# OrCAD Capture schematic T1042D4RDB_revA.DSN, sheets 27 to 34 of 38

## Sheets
27 27 PCIe: size B
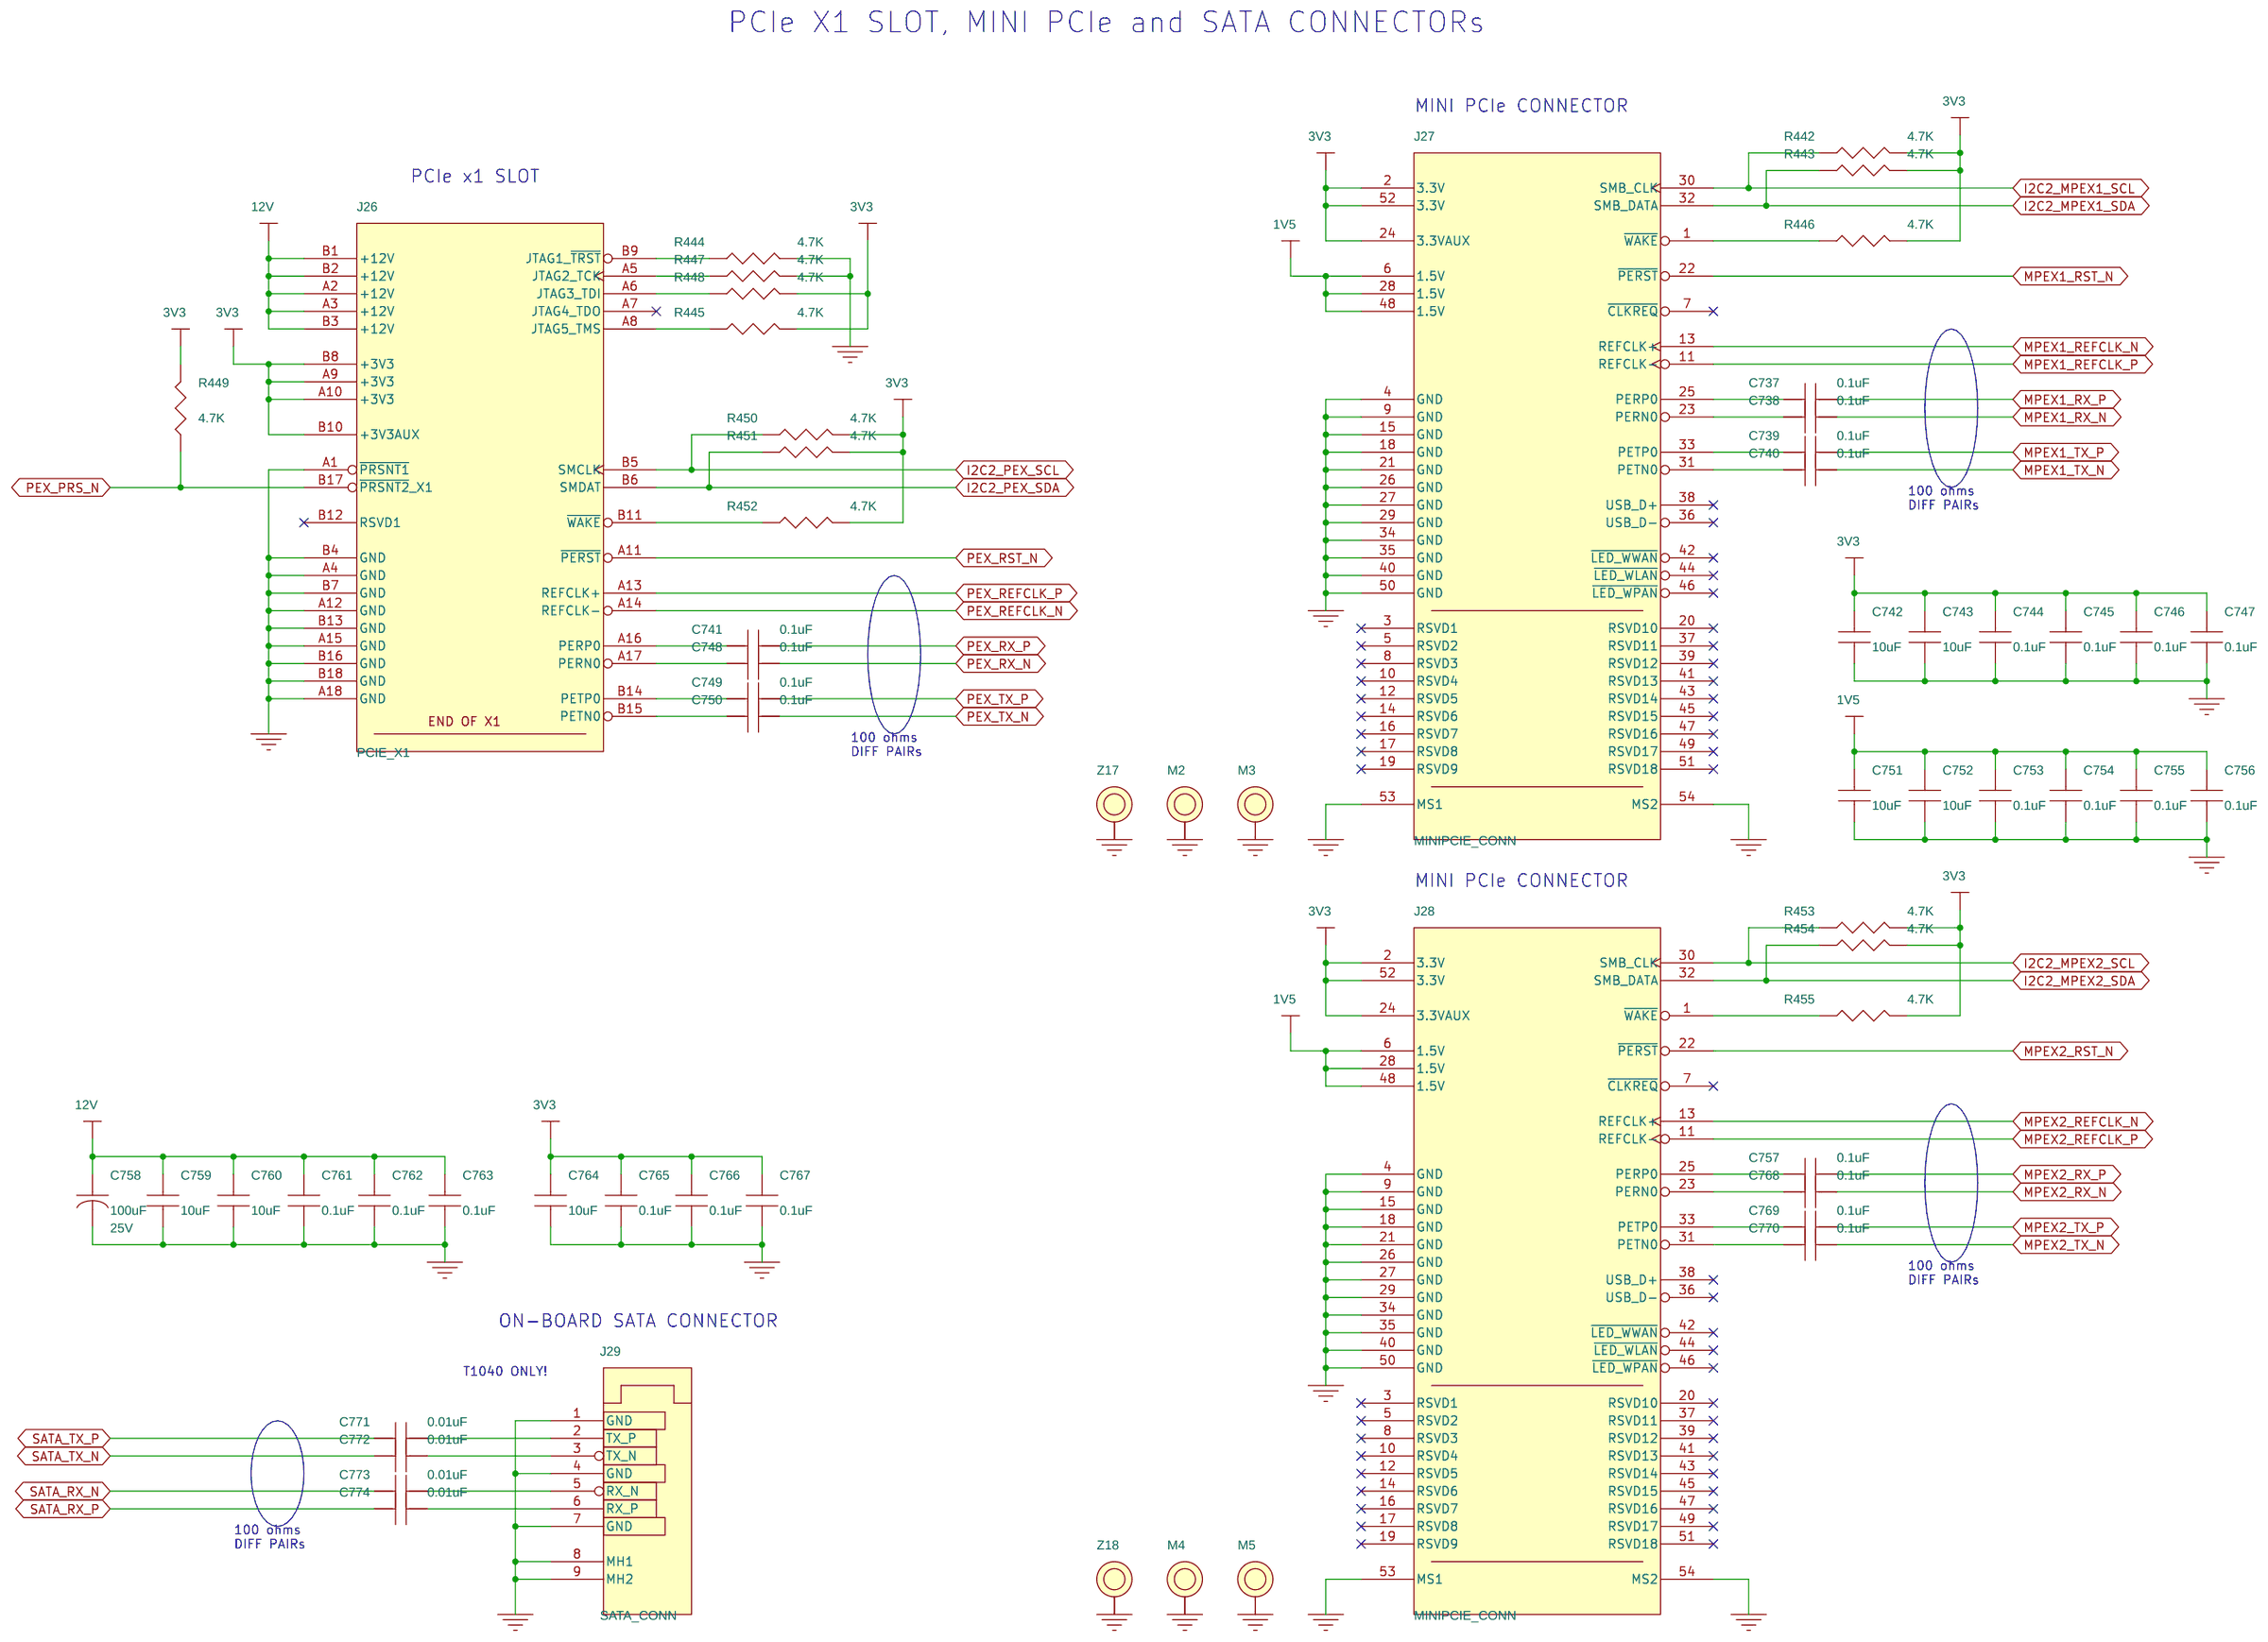
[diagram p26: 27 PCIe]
28 28 Aurora: size B
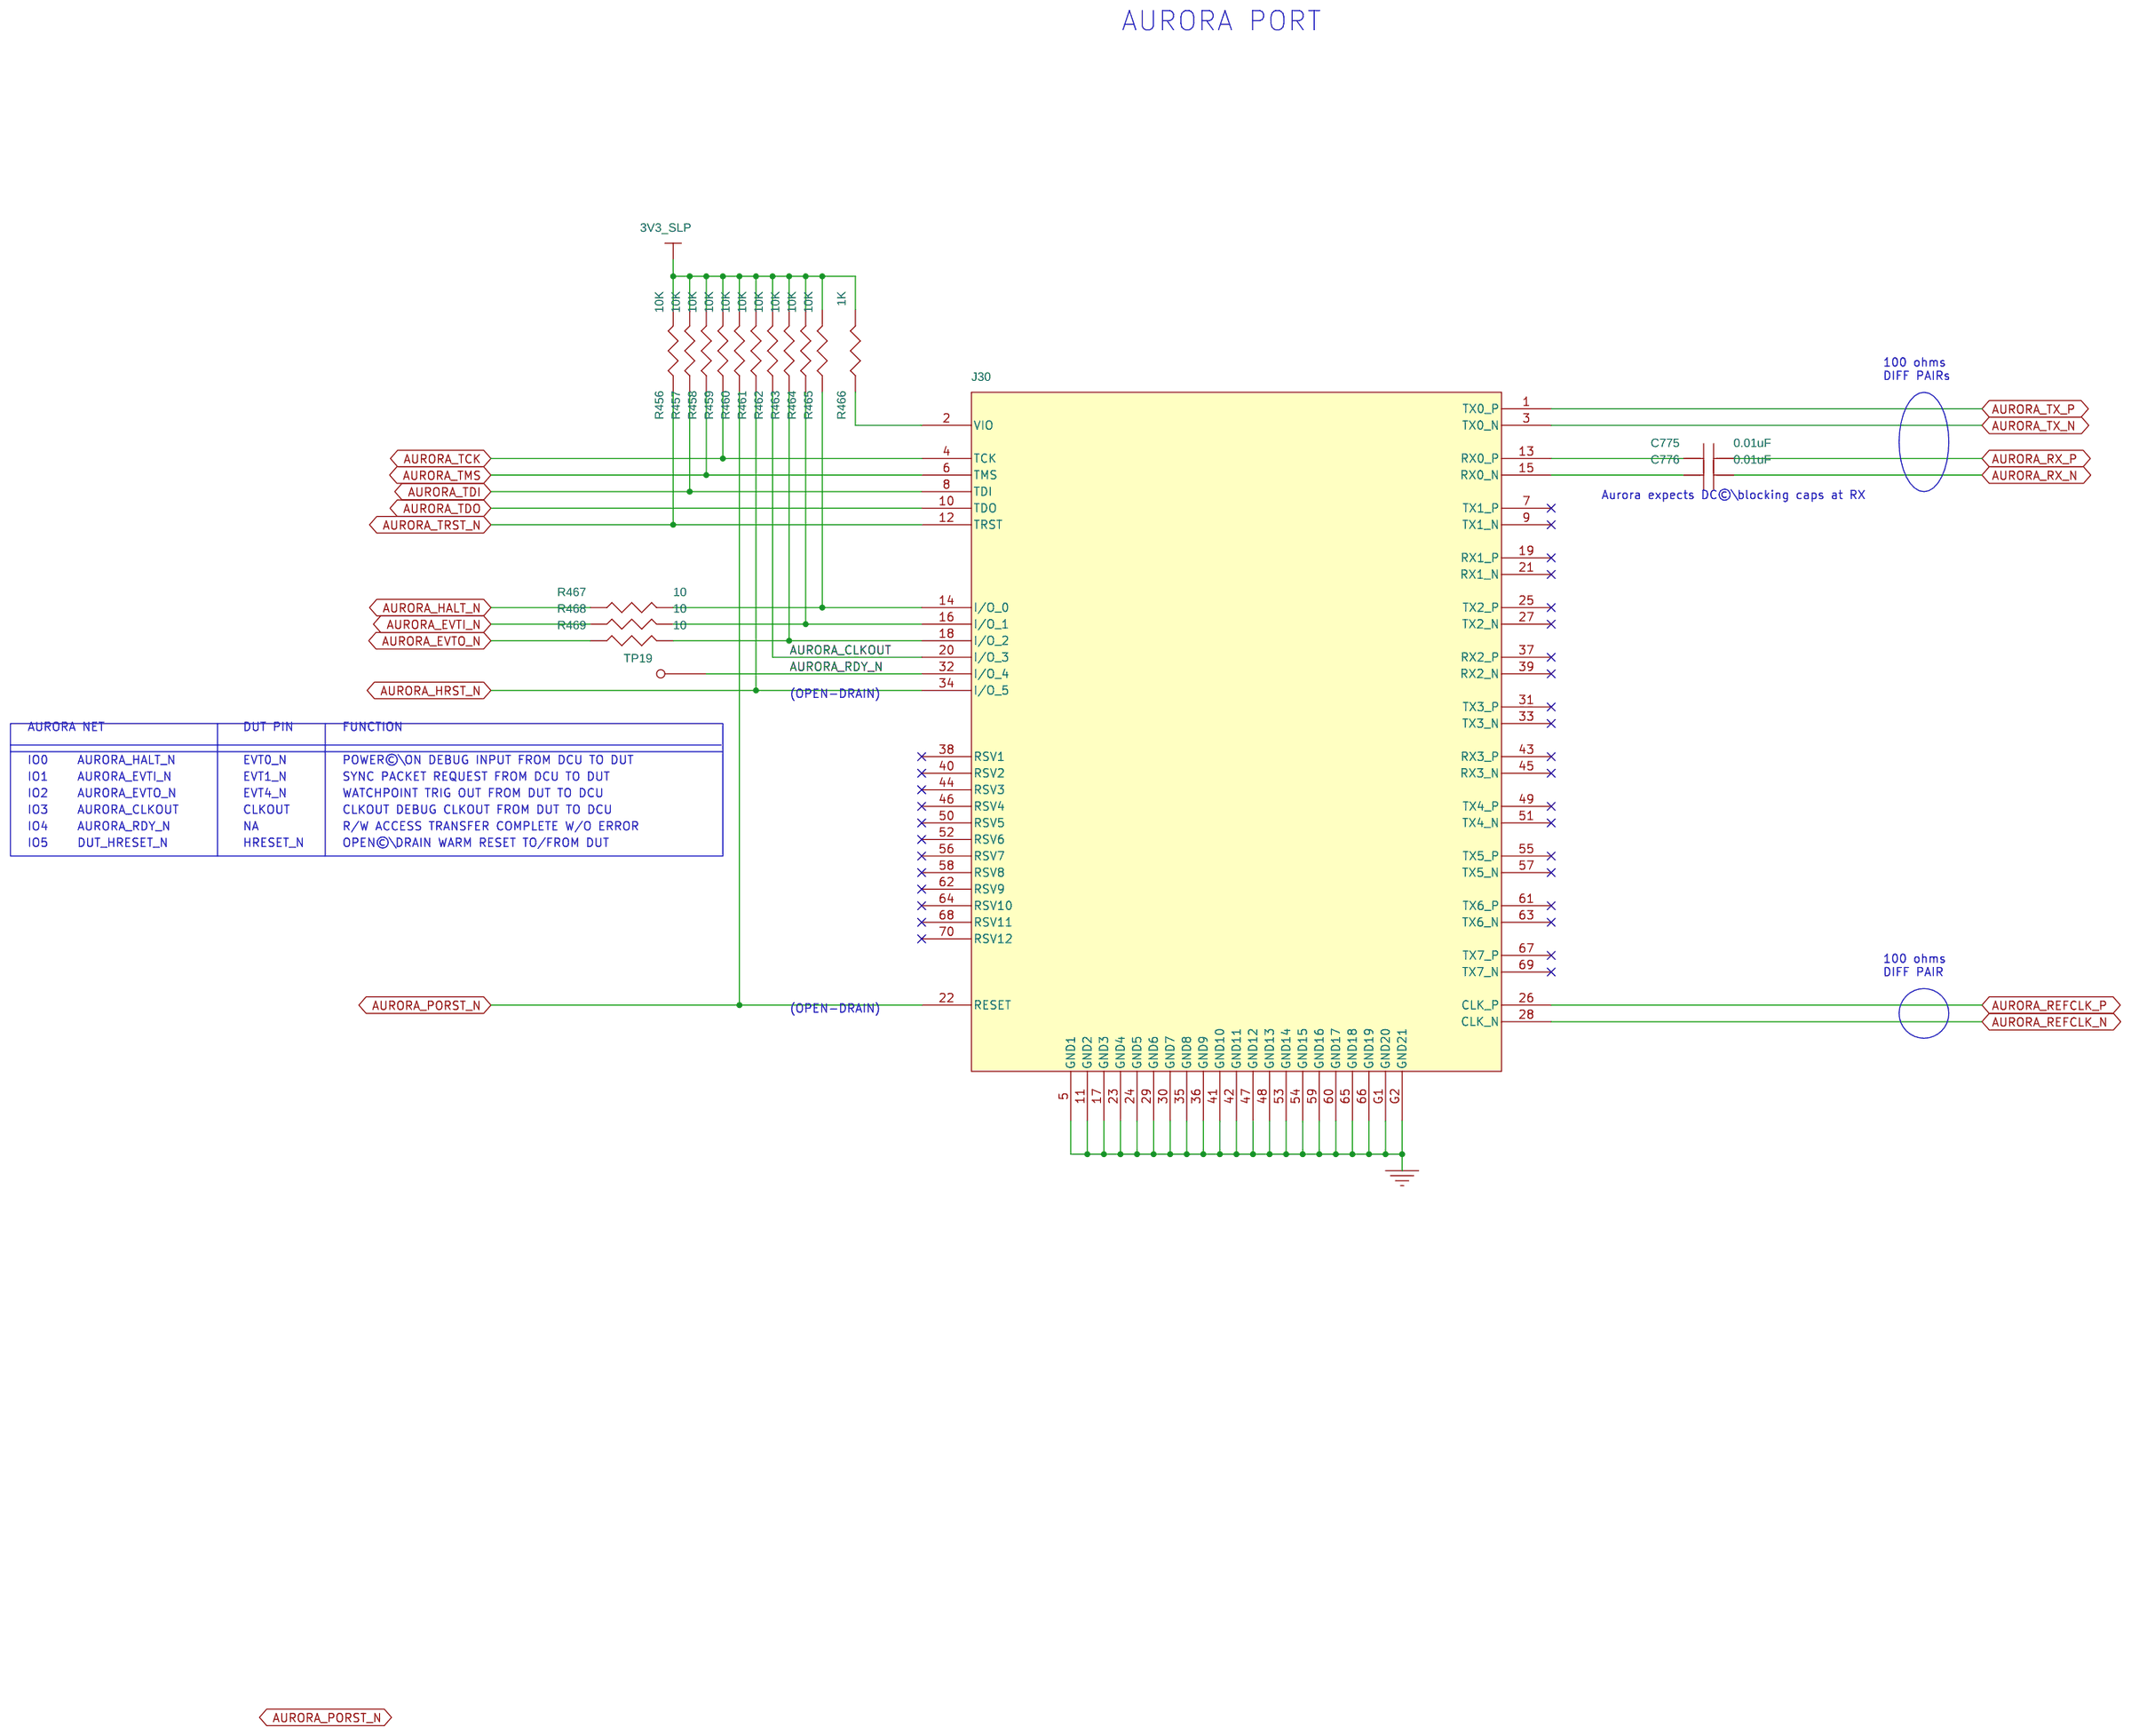
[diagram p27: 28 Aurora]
29 29 CPLD: size B
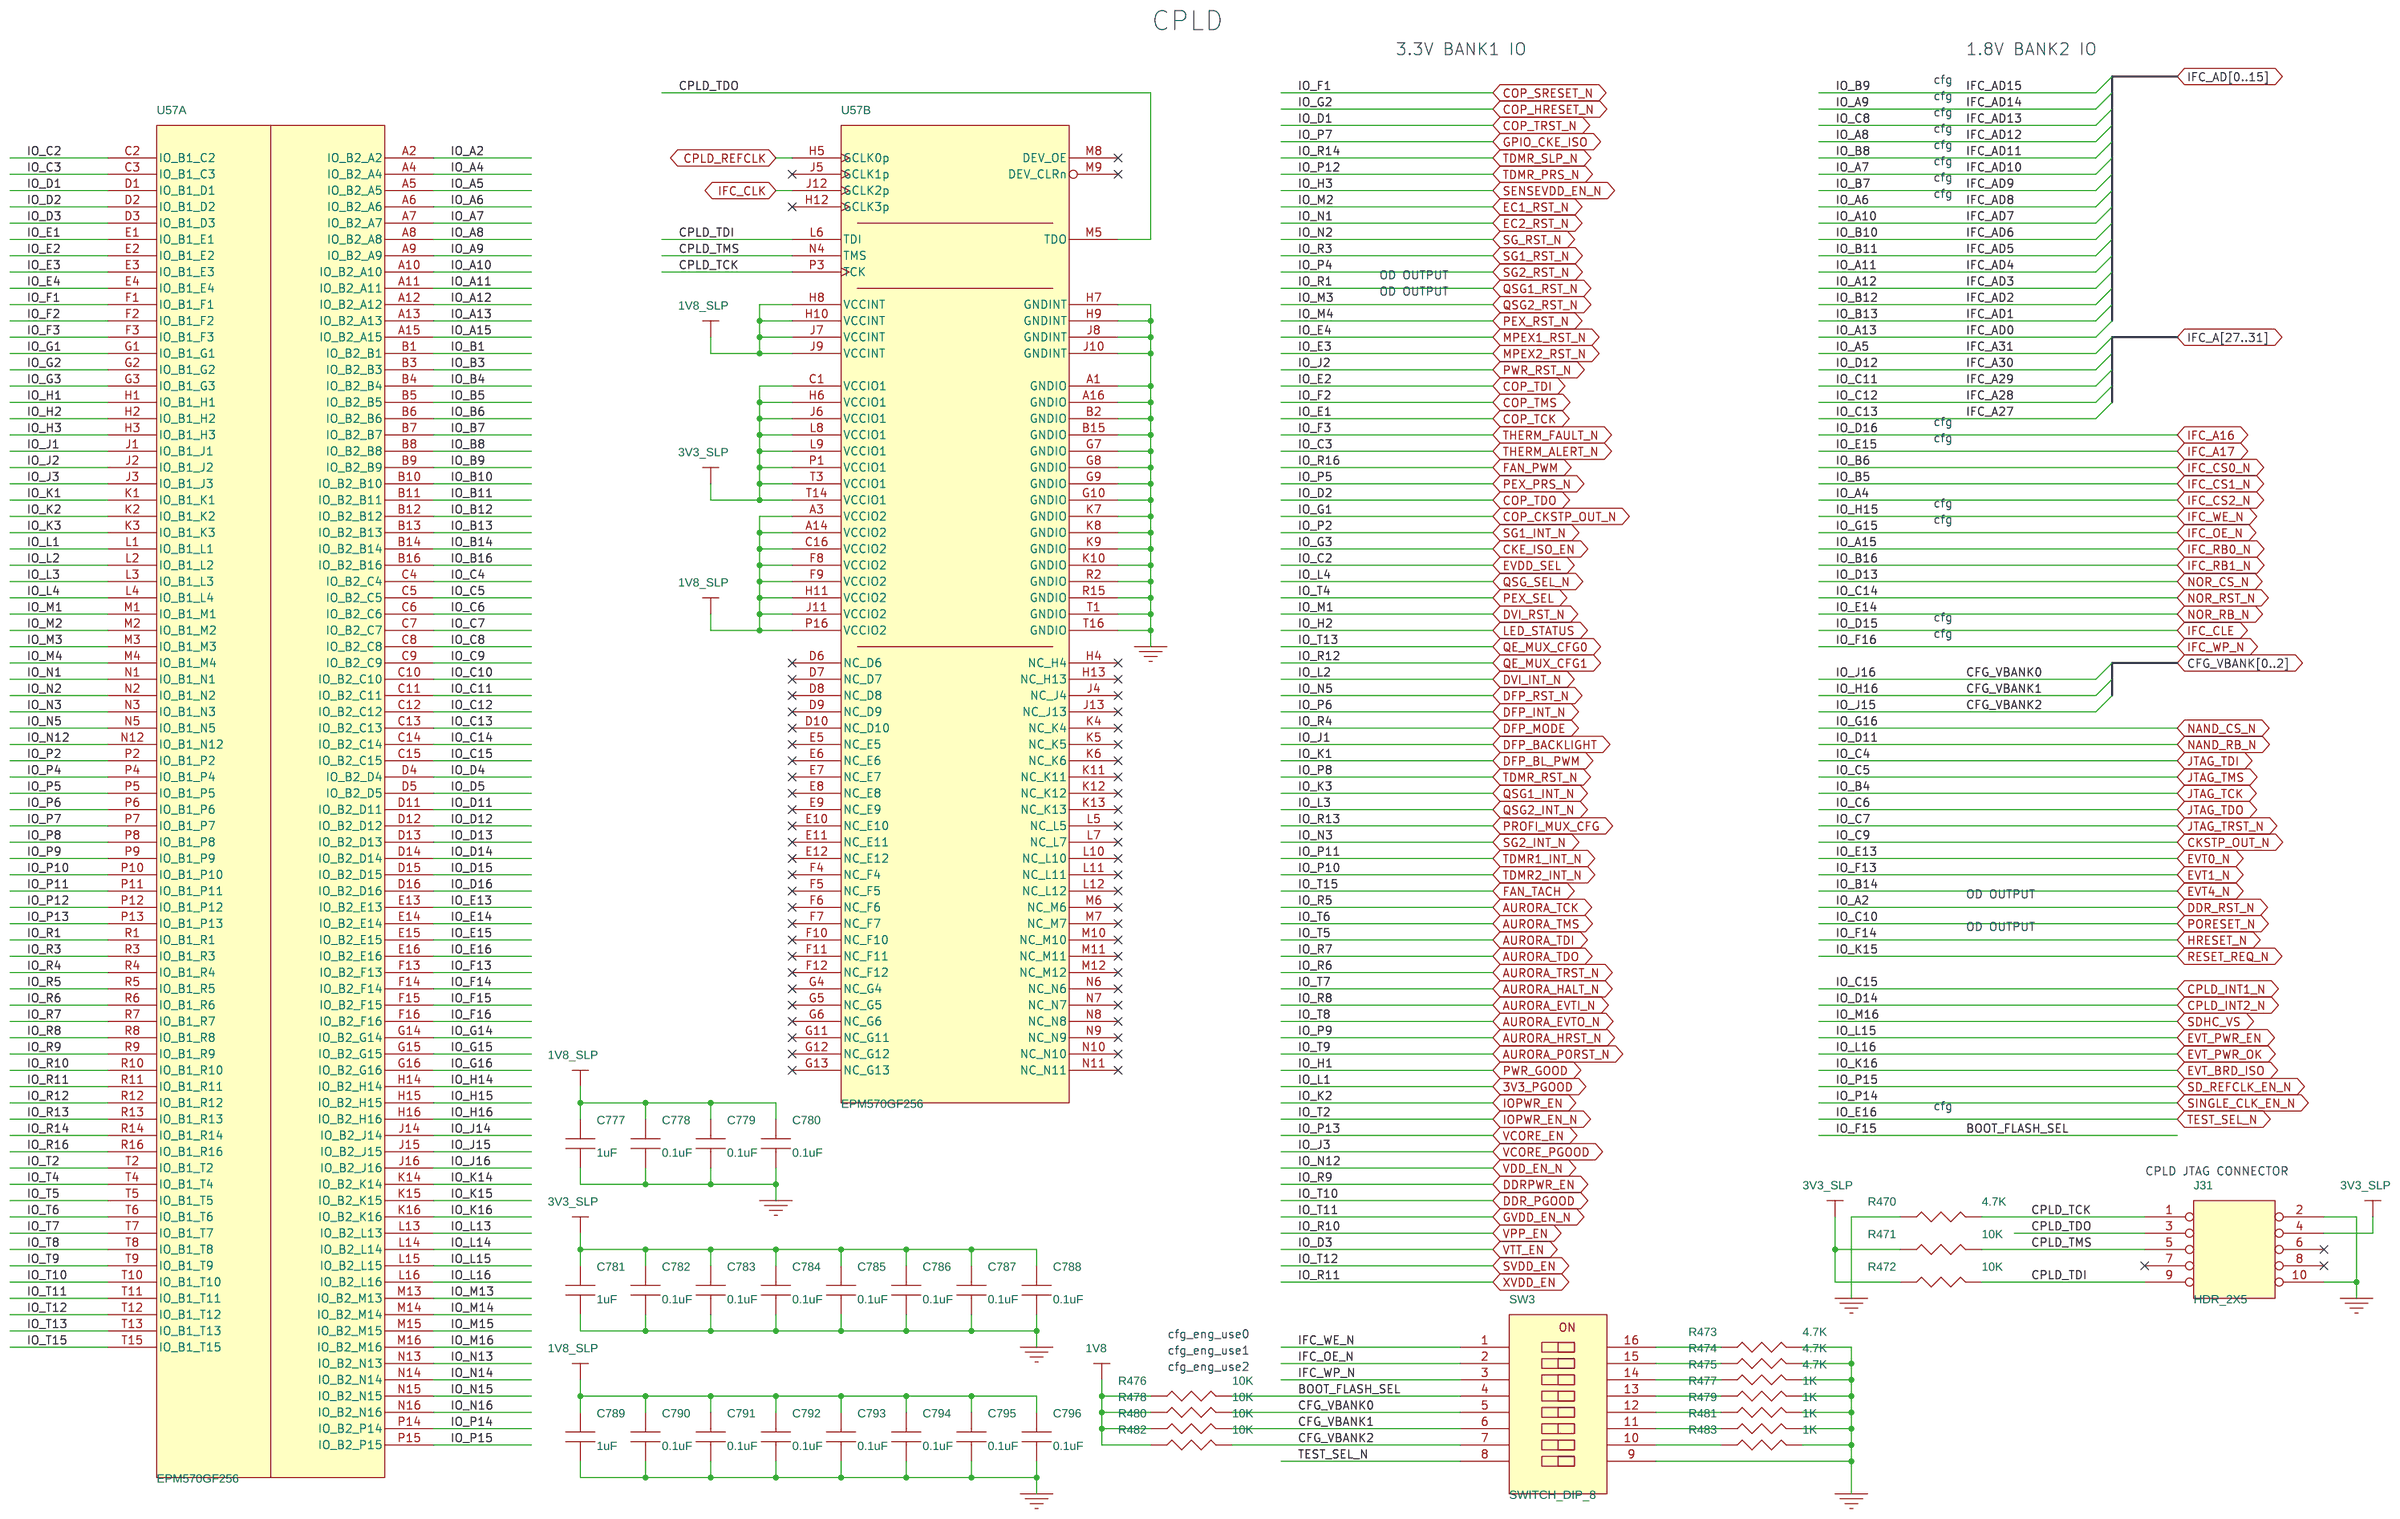
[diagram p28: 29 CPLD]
30 30 Clock 1: size B
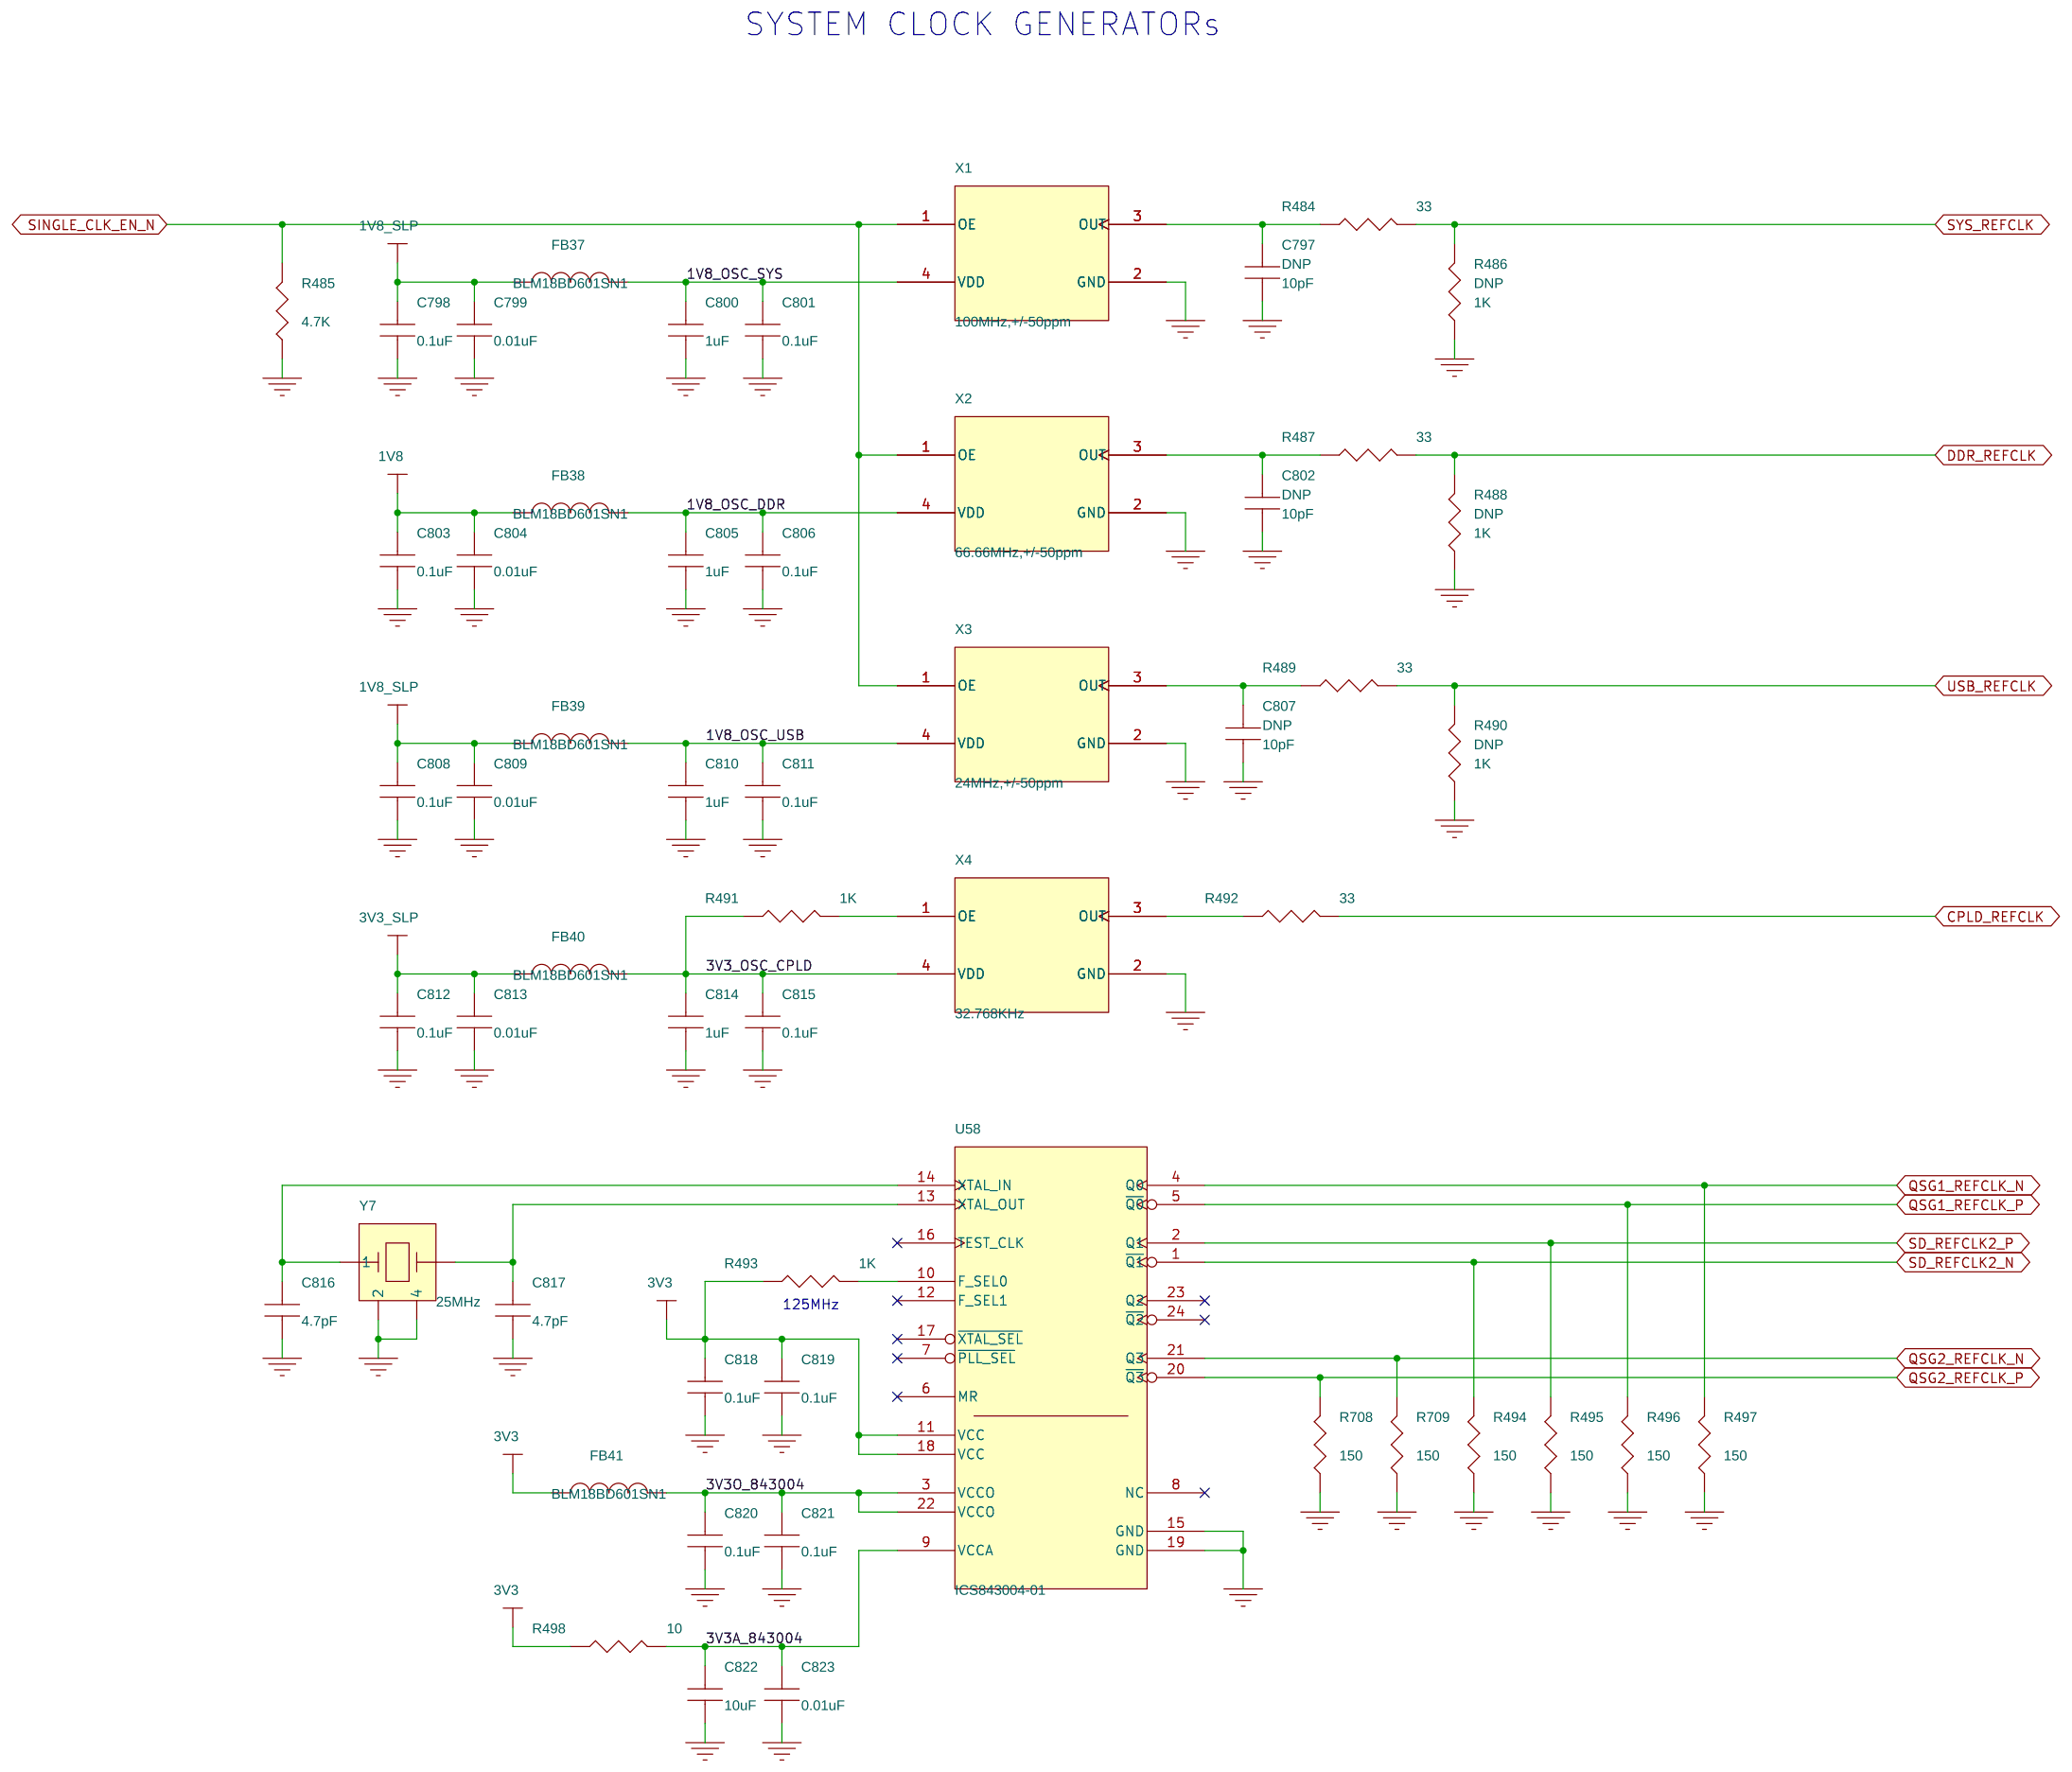
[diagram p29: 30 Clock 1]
31 31 Clock 2: size B
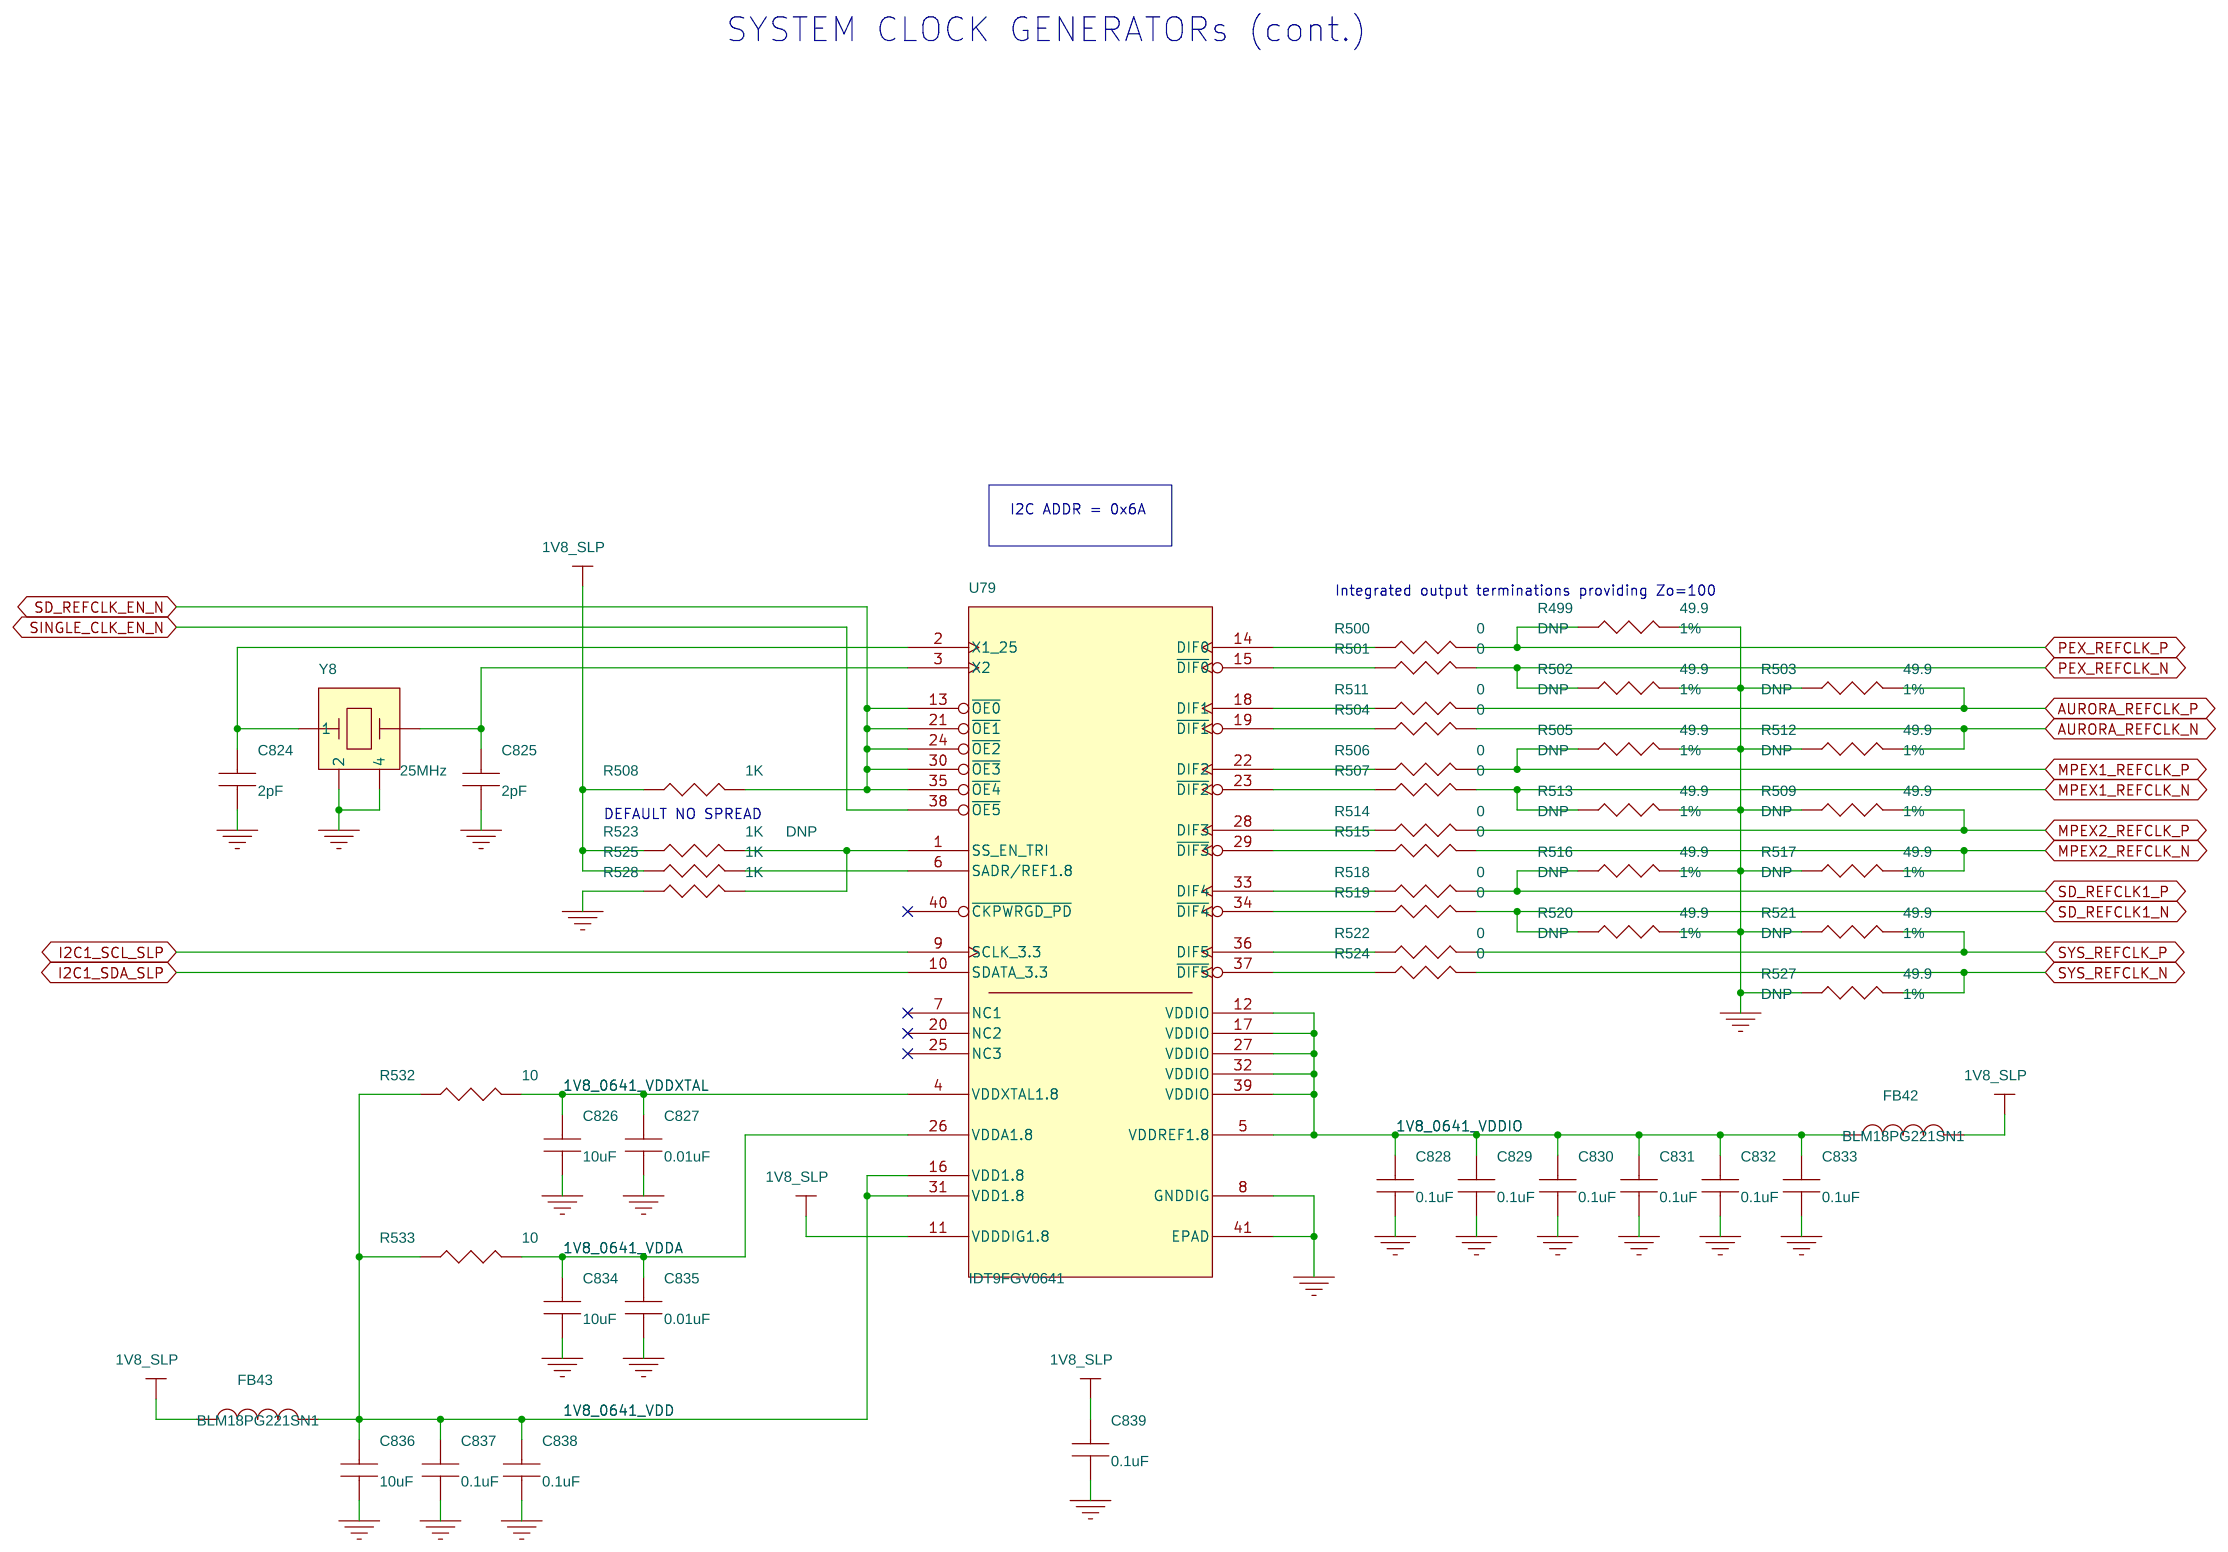
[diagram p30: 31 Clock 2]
32 32 Core Pwr: size B
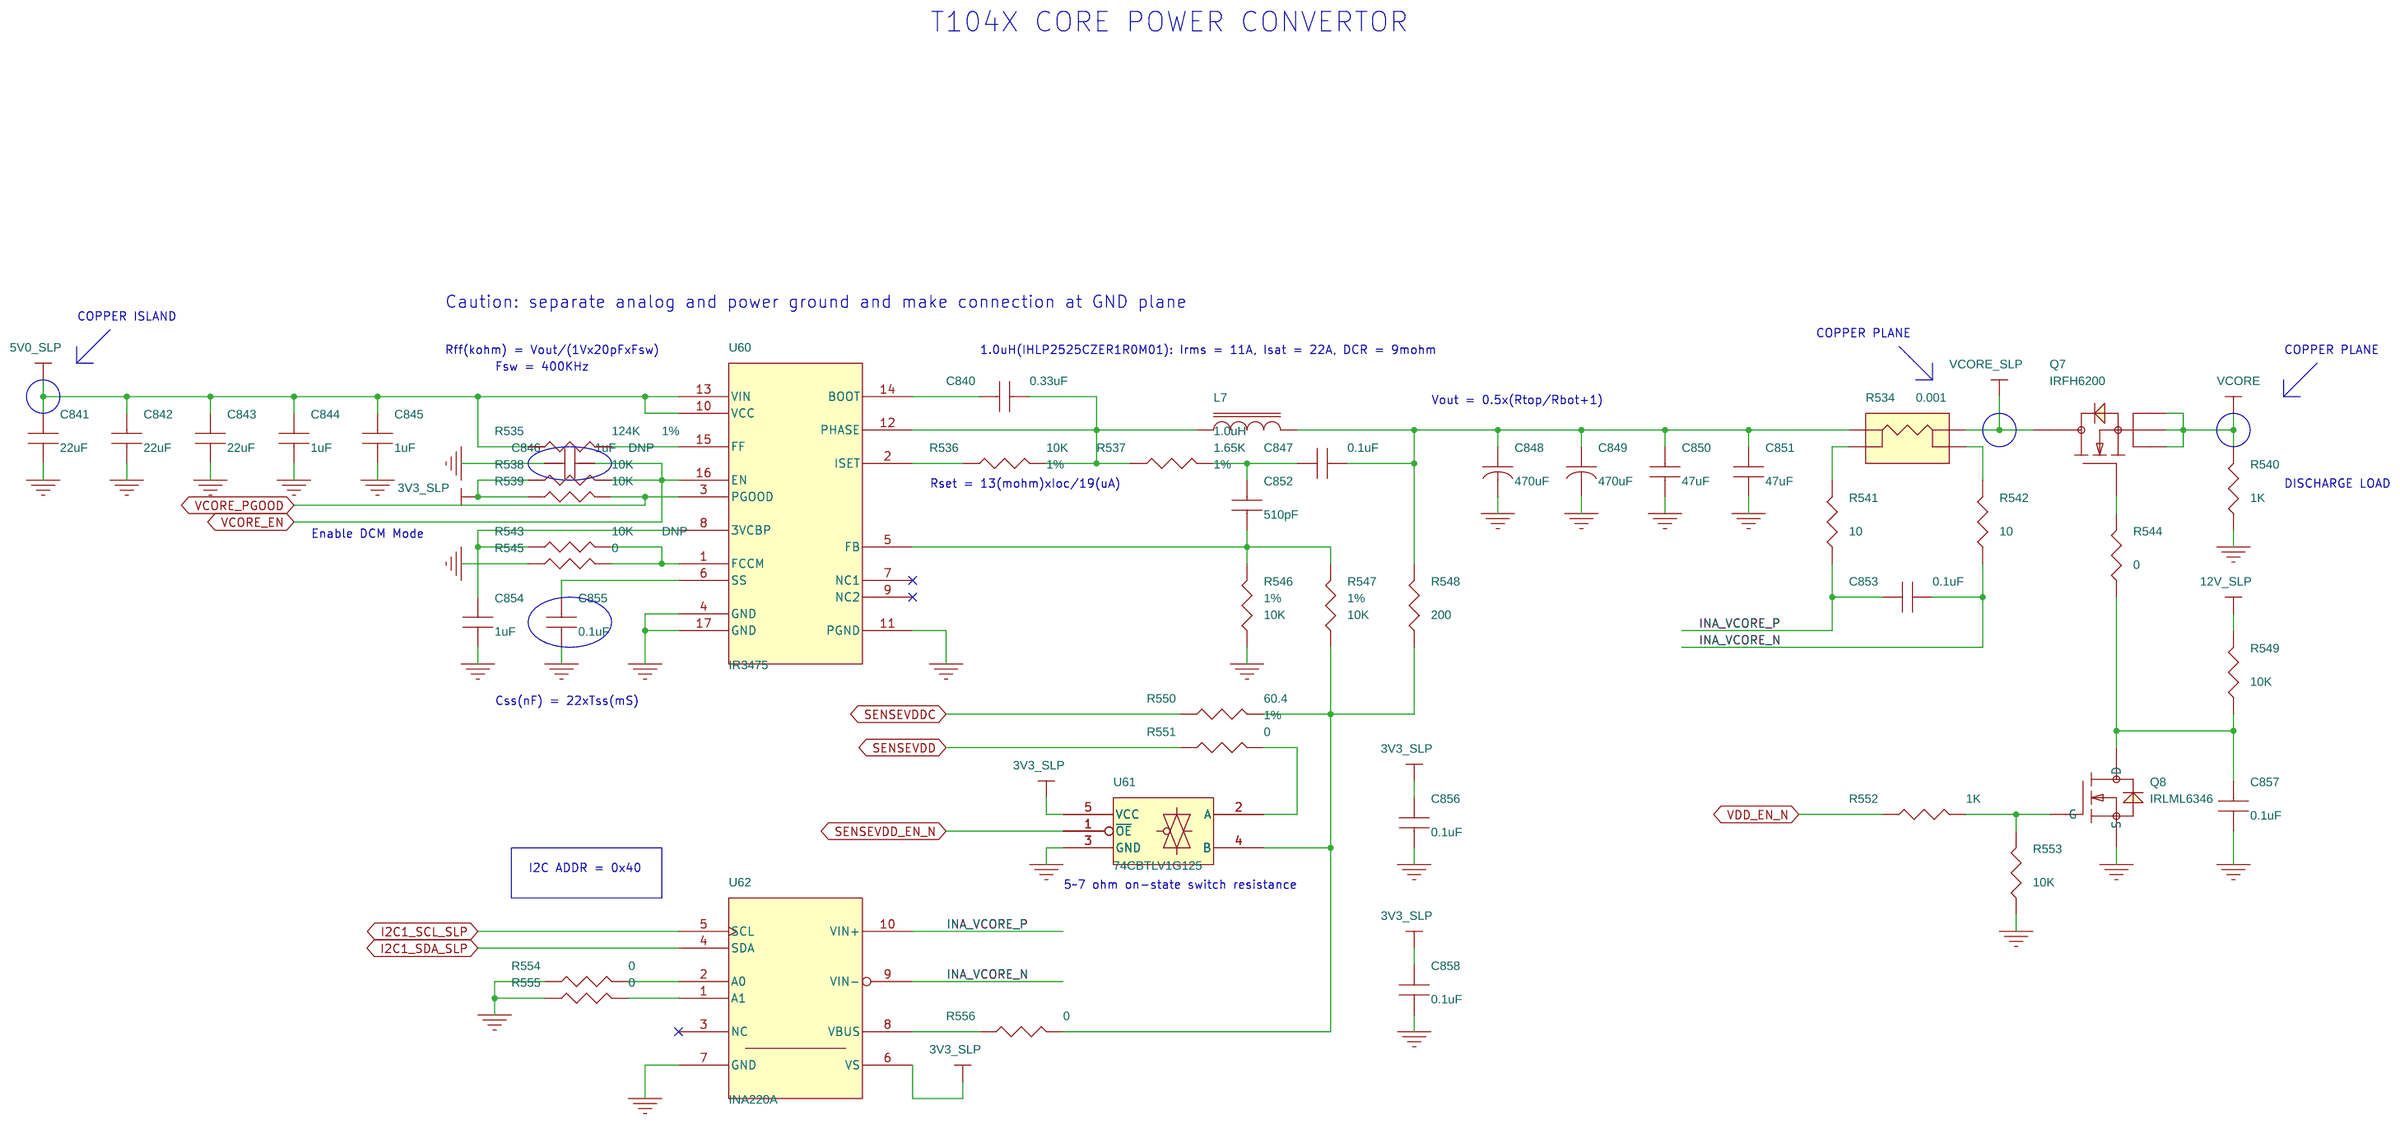
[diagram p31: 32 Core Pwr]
33 33 Other Pwr 1: size B
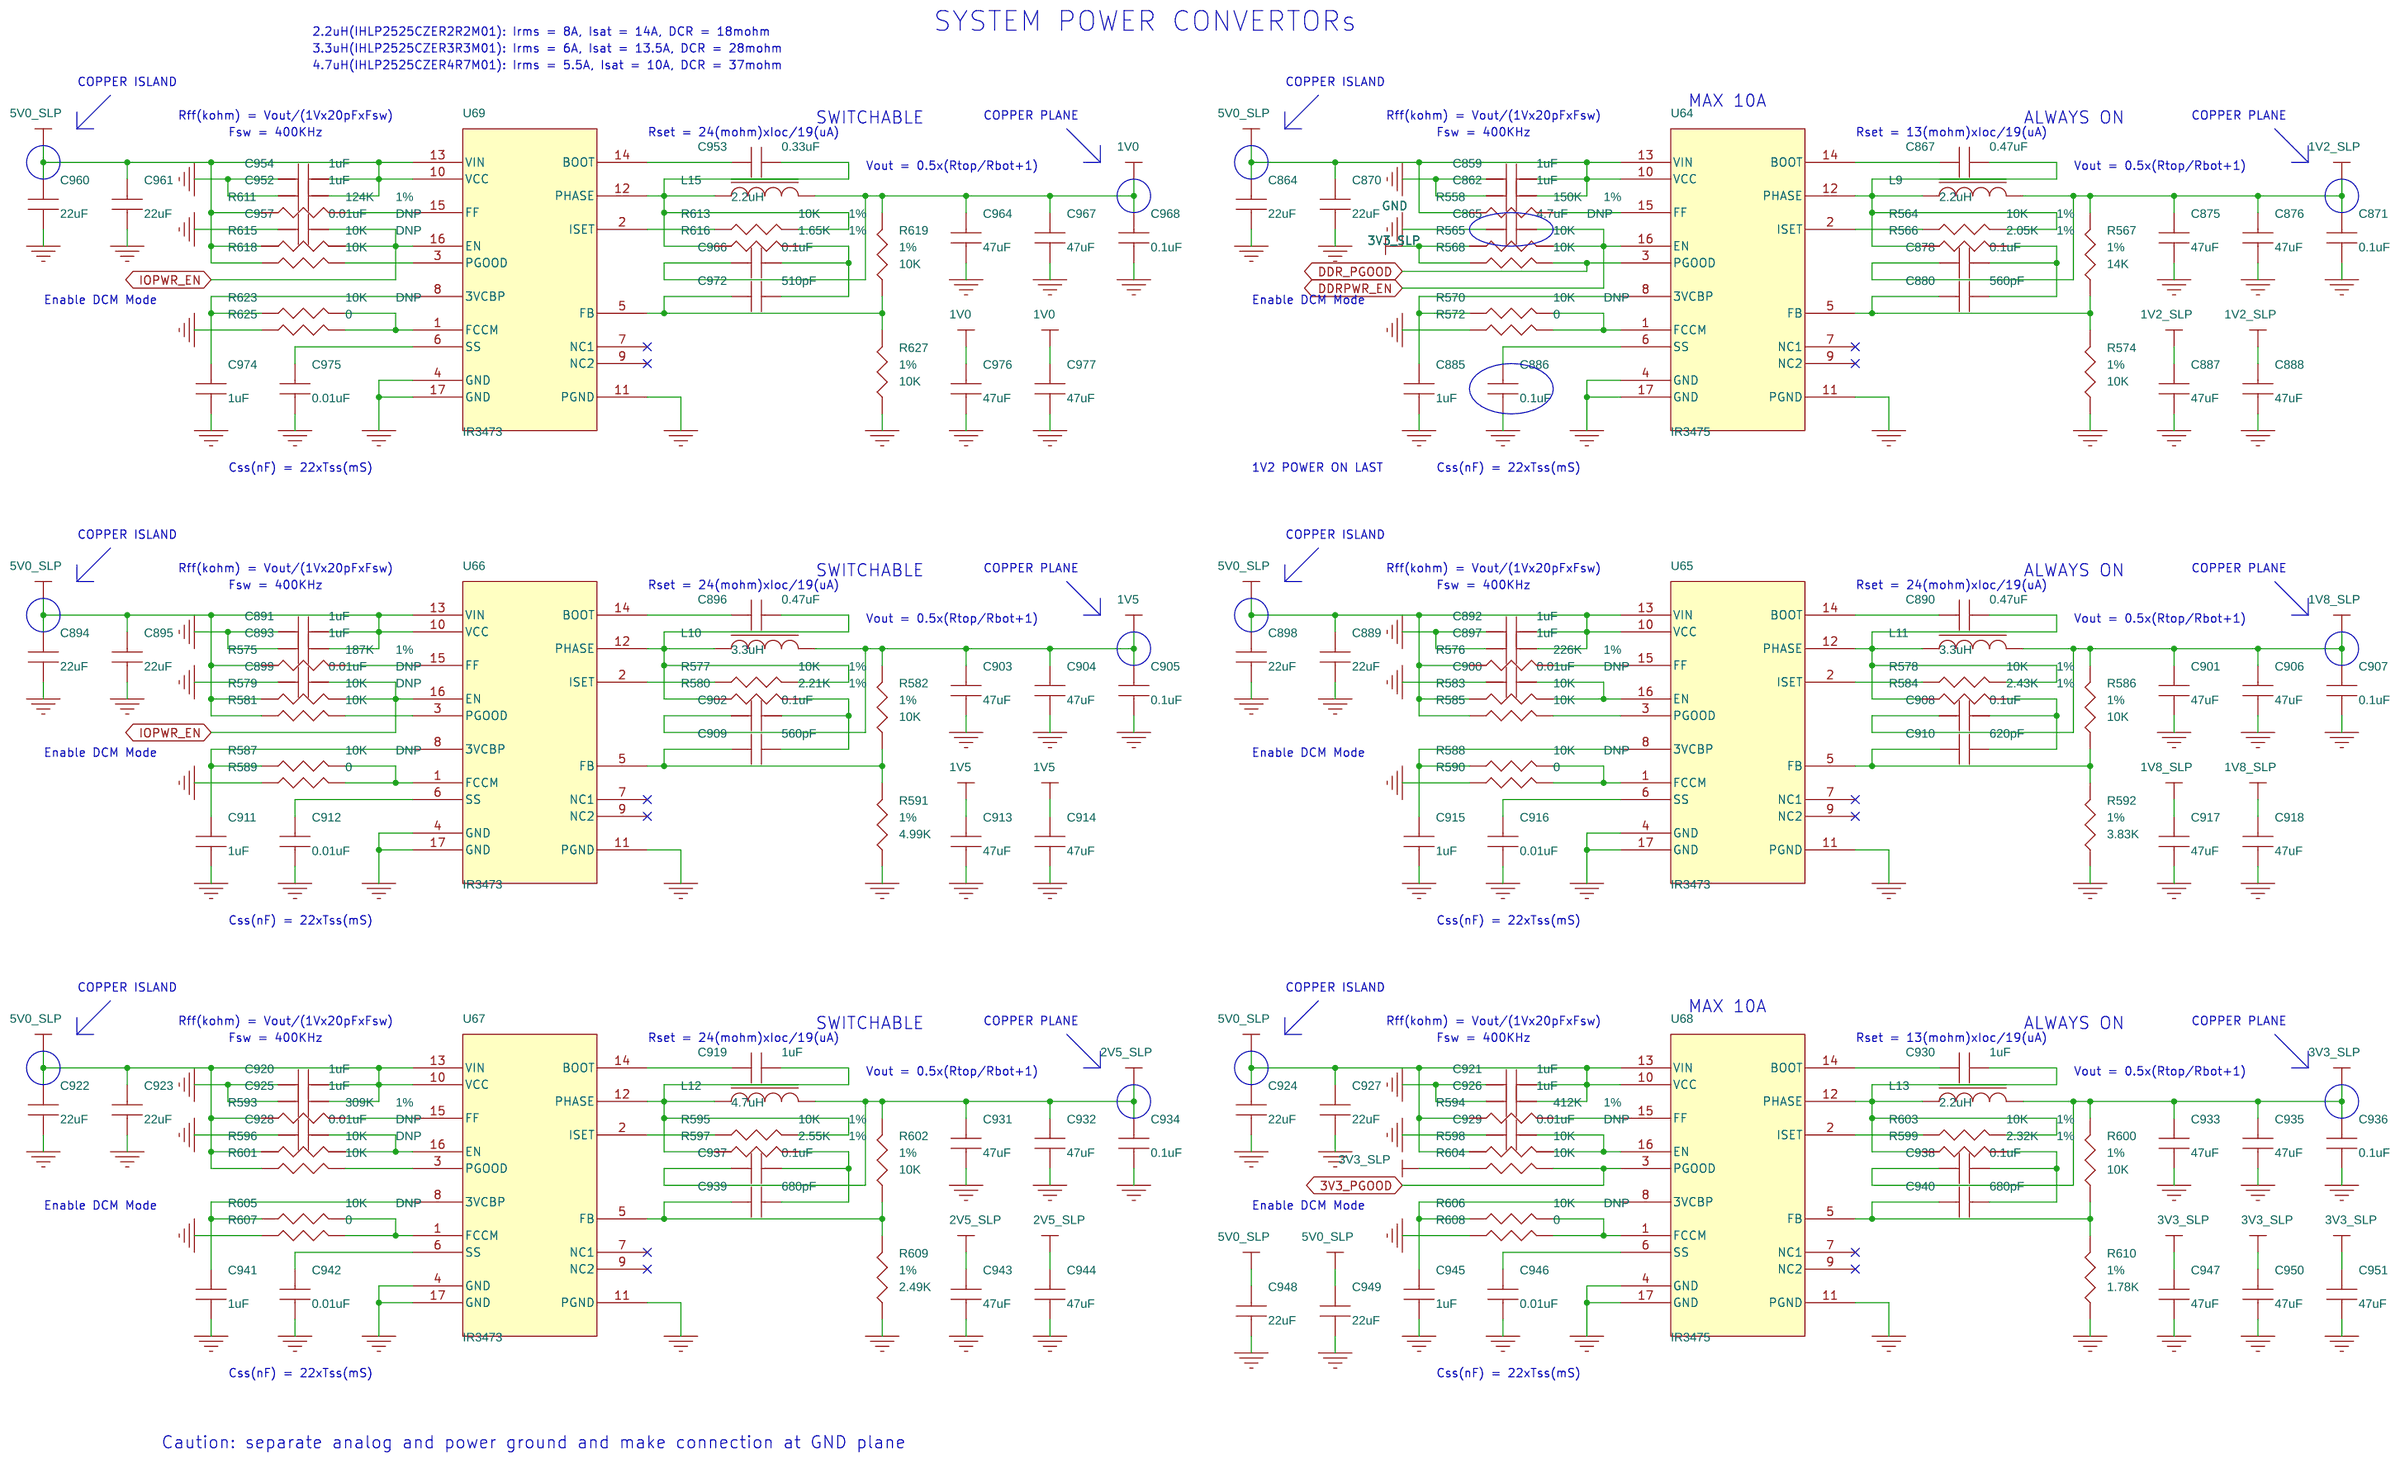
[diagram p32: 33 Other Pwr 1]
34 34 Other Pwr 2: size B
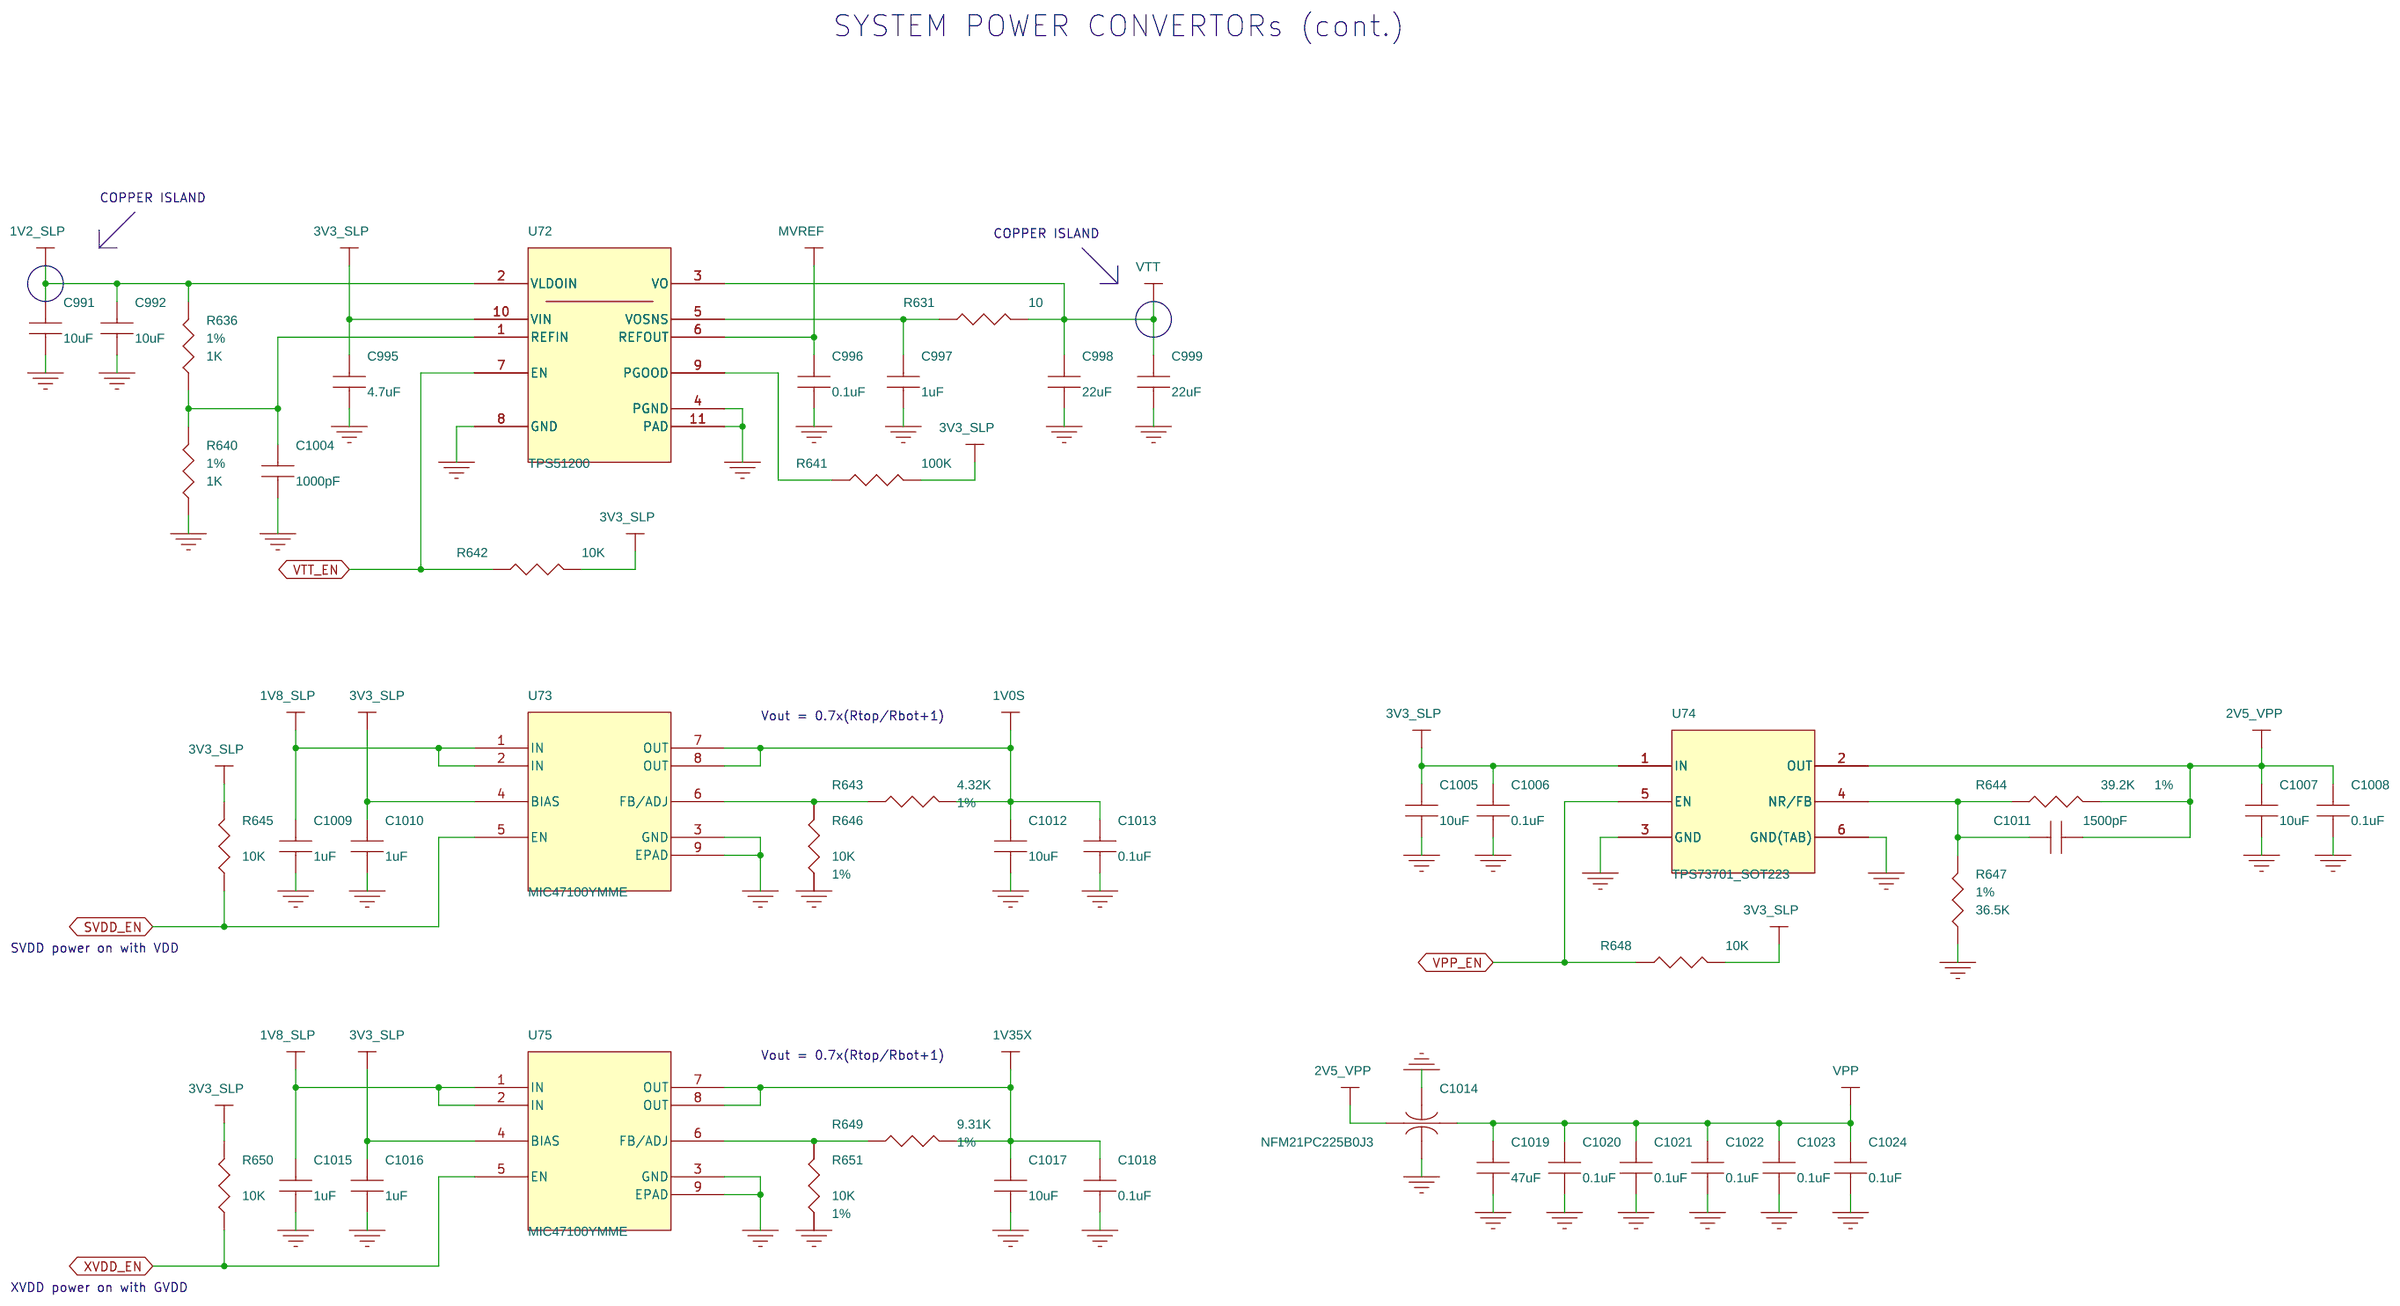
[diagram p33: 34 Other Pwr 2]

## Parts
sheet 27 PCIe
C737  0.1uF  [0402]
C738  0.1uF  [0402]
C739  0.1uF  [0402]
C740  0.1uF  [0402]
C741  0.1uF  [0402]
C742  10uF  [0603]
C743  10uF  [0603]
C744  0.1uF  [0402]
C745  0.1uF  [0402]
C746  0.1uF  [0402]
C747  0.1uF  [0402]
C748  0.1uF  [0402]
C749  0.1uF  [0402]
C750  0.1uF  [0402]
C751  10uF  [0603]
C752  10uF  [0603]
C753  0.1uF  [0402]
C754  0.1uF  [0402]
C755  0.1uF  [0402]
C756  0.1uF  [0402]
C757  0.1uF  [0402]
C758  100uF  [cape_b6d3]
C759  10uF  [1206]
C760  10uF  [1206]
C761  0.1uF  [0603]
C762  0.1uF  [0603]
C763  0.1uF  [0603]
C764  10uF  [0603]
C765  0.1uF  [0402]
C766  0.1uF  [0402]
C767  0.1uF  [0402]
C768  0.1uF  [0402]
C769  0.1uF  [0402]
C770  0.1uF  [0402]
C771  0.01uF  [0402]
C772  0.01uF  [0402]
C773  0.01uF  [0402]
C774  0.01uF  [0402]
J26  PCIE_X1  [con_pex1]
J27  MINIPCIE_CONN  [con_minipcie]
J28  MINIPCIE_CONN  [con_minipcie]
J29  SATA_CONN  [con_sata]
M2  MH  [mh_580s340p]
M3  MH  [mh_580s340p]
M4  MH  [mh_580s340p]
M5  MH  [mh_580s340p]
R442  4.7K  [0402]
R443  4.7K  [0402]
R444  4.7K  [0402]
R445  4.7K  [0402]
R446  4.7K  [0402]
R447  4.7K  [0402]
R448  4.7K  [0402]
R449  4.7K  [0402]
R450  4.7K  [0402]
R451  4.7K  [0402]
R452  4.7K  [0402]
R453  4.7K  [0402]
R454  4.7K  [0402]
R455  4.7K  [0402]
Z17  MH  [mh_680c320p]
Z18  MH  [mh_680c320p]
sheet 28 Aurora
C775  0.01uF  [0402]
C776  0.01uF  [0402]
J30  CONN SKT 70  [con2x35_skt_0p8_sm]
R456  10K  [0402]
R457  10K  [0402]
R458  10K  [0402]
R459  10K  [0402]
R460  10K  [0402]
R461  10K  [0402]
R462  10K  [0402]
R463  10K  [0402]
R464  10K  [0402]
R465  10K  [0402]
R466  1K  [0402]
R467  10  [0402]
R468  10  [0402]
R469  10  [0402]
TP19  TP  [tp]
sheet 29 CPLD
C777  1uF  [0402o]
C778  0.1uF  [0402o]
C779  0.1uF  [0402o]
C780  0.1uF  [0402o]
C781  1uF  [0402o]
C782  0.1uF  [0402o]
C783  0.1uF  [0402o]
C784  0.1uF  [0402o]
C785  0.1uF  [0402o]
C786  0.1uF  [0402o]
C787  0.1uF  [0402o]
C788  0.1uF  [0402o]
C789  1uF  [0402o]
C790  0.1uF  [0402o]
C791  0.1uF  [0402o]
C792  0.1uF  [0402o]
C793  0.1uF  [0402o]
C794  0.1uF  [0402o]
C795  0.1uF  [0402o]
C796  0.1uF  [0402o]
J31  HDR_2X5  [hdr_p254_m_t_2x5]
R470  4.7K  [0402]
R471  10K  [0402]
R472  10K  [0402]
R473  4.7K  [0402]
R474  4.7K  [0402]
R475  4.7K  [0402]
R476  10K  [0402]
R477  1K  [0402]
R478  10K  [0402]
R479  1K  [0402]
R480  10K  [0402]
R481  1K  [0402]
R482  10K  [0402]
R483  1K  [0402]
SW3  SWITCH_DIP_8  [con_switch_x8]
U57  EPM570GF256  [bga_p100_256]  (sections A,B)
sheet 30 Clock 1
C797  10pF  [0402]
C798  0.1uF  [0402]
C799  0.01uF  [0402]
C800  1uF  [0402]
C801  0.1uF  [0402]
C802  10pF  [0402]
C803  0.1uF  [0402]
C804  0.01uF  [0402]
C805  1uF  [0402]
C806  0.1uF  [0402]
C807  10pF  [0402]
C808  0.1uF  [0402]
C809  0.01uF  [0402]
C810  1uF  [0402]
C811  0.1uF  [0402]
C812  0.1uF  [0402]
C813  0.01uF  [0402]
C814  1uF  [0402]
C815  0.1uF  [0402]
C816  4.7pF  [0402]
C817  4.7pF  [0402]
C818  0.1uF  [0402]
C819  0.1uF  [0402]
C820  0.1uF  [0402]
C821  0.1uF  [0402]
C822  10uF  [0603]
C823  0.01uF  [0402]
FB37  BLM18BD601SN1  [0603]
FB38  BLM18BD601SN1  [0603]
FB39  BLM18BD601SN1  [0603]
FB40  BLM18BD601SN1  [0603]
FB41  BLM18BD601SN1  [0603]
R484  33  [0402]
R485  4.7K  [0402]
R486  1K  [0402]
R487  33  [0402]
R488  1K  [0402]
R489  33  [0402]
R490  1K  [0402]
R491  1K  [0402]
R492  33  [0402]
R493  1K  [0402]
R494  150  [0402]
R495  150  [0402]
R496  150  [0402]
R497  150  [0402]
R498  10  [0402]
R708  150  [0402]
R709  150  [0402]
U58  ICS843004-01  [tssop_24]
X1  100MHz,+/-50ppm  [osc_7x5_4]
X2  66.66MHz,+/-50ppm  [osc_7x5_4]
X3  24MHz,+/-50ppm  [osc_7x5_4]
X4  32.768KHz  [osc_32x25_4]
Y7  25MHz  [cry_32x25_4]
sheet 31 Clock 2
C824  2pF  [0402]
C825  2pF  [0402]
C826  10uF  [0603]
C827  0.01uF  [0402]
C828  0.1uF  [0402]
C829  0.1uF  [0402]
C830  0.1uF  [0402]
C831  0.1uF  [0402]
C832  0.1uF  [0402]
C833  0.1uF  [0402]
C834  10uF  [0603]
C835  0.01uF  [0402]
C836  10uF  [0603]
C837  0.1uF  [0402]
C838  0.1uF  [0402]
C839  0.1uF  [0402]
FB42  BLM18PG221SN1  [0603]
FB43  BLM18PG221SN1  [0603]
R499  49.9  [0402]
R500  0  [0402]
R501  0  [0402]
R502  49.9  [0402]
R503  49.9  [0402]
R504  0  [0402]
R505  49.9  [0402]
R506  0  [0402]
R507  0  [0402]
R508  1K  [0402]
R509  49.9  [0402]
R511  0  [0402]
R512  49.9  [0402]
R513  49.9  [0402]
R514  0  [0402]
R515  0  [0402]
R516  49.9  [0402]
R517  49.9  [0402]
R518  0  [0402]
R519  0  [0402]
R520  49.9  [0402]
R521  49.9  [0402]
R522  0  [0402]
R523  1K  [0402]
R524  0  [0402]
R525  1K  [0402]
R527  49.9  [0402]
R528  1K  [0402]
R532  10  [0402]
R533  10  [0402]
U79  IDT9FGV0641  [qfn_p040_d040_b500_40_e370]
Y8  25MHz  [cry_32x25_4]
sheet 32 Core Pwr
C840  0.33uF  [0603]
C841  22uF  [1206]
C842  22uF  [1206]
C843  22uF  [1206]
C844  1uF  [0603]
C845  1uF  [0603]
C846  1uF  [0402]
C847  0.1uF  [0402]
C848  470uF  [7343]
C849  470uF  [7343]
C850  47uF  [0805]
C851  47uF  [0805]
C852  510pF  [0402]
C853  0.1uF  [0402]
C854  1uF  [0402]
C855  0.1uF  [0402]
C856  0.1uF  [0402]
C857  0.1uF  [0402]
C858  0.1uF  [0402]
L7  1.0uH  [ind_ihlp_4040]
Q7  IRFH6200  [so_8_fl]
Q8  IRLML6346  [sot23]
R534  0.001  [res_wsl2726]
R535  124K  [0402]
R536  10K  [0402]
R537  1.65K  [0402]
R538  10K  [0402]
R539  10K  [0402]
R540  1K  [0402]
R541  10  [0402]
R542  10  [0402]
R543  10K  [0402]
R544  0  [0402]
R545  0  [0402]
R546  10K  [0402]
R547  10K  [0402]
R548  200  [0402]
R549  10K  [0402]
R550  60.4  [0402]
R551  0  [0402]
R552  1K  [0402]
R553  10K  [0402]
R554  0  [0402]
R555  0  [0402]
R556  0  [0402]
U60  IR3475  [qfn_supirbuck_4x5]
U61  74CBTLV1G125  [sc70_5]
U62  INA220A  [msop_10]
sheet 33 Other Pwr 1
C859  1uF  [0603]
C862  1uF  [0603]
C864  22uF  [1206]
C865  4.7uF  [0603]
C867  0.47uF  [0603]
C870  22uF  [1206]
C871  0.1uF  [0402]
C875  47uF  [0805]
C876  47uF  [0805]
C878  0.1uF  [0402]
C880  560pF  [0402]
C885  1uF  [0402]
C886  0.1uF  [0402]
C887  47uF  [0805]
C888  47uF  [0805]
C889  22uF  [1206]
C890  0.47uF  [0603]
C891  1uF  [0603]
C892  1uF  [0603]
C893  1uF  [0603]
C894  22uF  [1206]
C895  22uF  [1206]
C896  0.47uF  [0603]
C897  1uF  [0603]
C898  22uF  [1206]
C899  0.01uF  [0402]
C900  0.01uF  [0402]
C901  47uF  [0805]
C902  0.1uF  [0402]
C903  47uF  [0805]
C904  47uF  [0805]
C905  0.1uF  [0402]
C906  47uF  [0805]
C907  0.1uF  [0402]
C908  0.1uF  [0402]
C909  560pF  [0402]
C910  620pF  [0402]
C911  1uF  [0402]
C912  0.01uF  [0402]
C913  47uF  [0805]
C914  47uF  [0805]
C915  1uF  [0402]
C916  0.01uF  [0402]
C917  47uF  [0805]
C918  47uF  [0805]
C919  1uF  [0603]
C920  1uF  [0603]
C921  1uF  [0603]
C922  22uF  [1206]
C923  22uF  [1206]
C924  22uF  [1206]
C925  1uF  [0603]
C926  1uF  [0603]
C927  22uF  [1206]
C928  0.01uF  [0402]
C929  0.01uF  [0402]
C930  1uF  [0603]
C931  47uF  [0805]
C932  47uF  [0805]
C933  47uF  [0805]
C934  0.1uF  [0402]
C935  47uF  [0805]
C936  0.1uF  [0402]
C937  0.1uF  [0402]
C938  0.1uF  [0402]
C939  680pF  [0402]
C940  680pF  [0402]
C941  1uF  [0402]
C942  0.01uF  [0402]
C943  47uF  [0805]
C944  47uF  [0805]
C945  1uF  [0402]
C946  0.01uF  [0402]
C947  47uF  [0805]
C948  22uF  [1206]
C949  22uF  [1206]
C950  47uF  [0805]
C951  47uF  [0805]
C952  1uF  [0603]
C953  0.33uF  [0603]
C954  1uF  [0603]
C957  0.01uF  [0402]
C960  22uF  [1206]
C961  22uF  [1206]
C964  47uF  [0805]
C966  0.1uF  [0402]
C967  47uF  [0805]
C968  0.1uF  [0402]
C972  510pF  [0402]
C974  1uF  [0402]
C975  0.01uF  [0402]
C976  47uF  [0805]
C977  47uF  [0805]
L9  2.2uH  [ind_ihlp_2525]
L10  3.3uH  [ind_ihlp_2525]
L11  3.3uH  [ind_ihlp_2525]
L12  4.7uH  [ind_ihlp_2525]
L13  2.2uH  [ind_ihlp_2525]
L15  2.2uH  [ind_ihlp_2525]
R558  150K  [0402]
R564  10K  [0402]
R565  10K  [0402]
R566  2.05K  [0402]
R567  14K  [0402]
R568  10K  [0402]
R570  10K  [0402]
R572  0  [0402]
R574  10K  [0402]
R575  187K  [0402]
R576  226K  [0402]
R577  10K  [0402]
R578  10K  [0402]
R579  10K  [0402]
R580  2.21K  [0402]
R581  10K  [0402]
R582  10K  [0402]
R583  10K  [0402]
R584  2.43K  [0402]
R585  10K  [0402]
R586  10K  [0402]
R587  10K  [0402]
R588  10K  [0402]
R589  0  [0402]
R590  0  [0402]
R591  4.99K  [0402]
R592  3.83K  [0402]
R593  309K  [0402]
R594  412K  [0402]
R595  10K  [0402]
R596  10K  [0402]
R597  2.55K  [0402]
R598  10K  [0402]
R599  2.32K  [0402]
R600  10K  [0402]
R601  10K  [0402]
R602  10K  [0402]
R603  10K  [0402]
R604  10K  [0402]
R605  10K  [0402]
R606  10K  [0402]
R607  0  [0402]
R608  0  [0402]
R609  2.49K  [0402]
R610  1.78K  [0402]
R611  124K  [0402]
R613  10K  [0402]
R615  10K  [0402]
R616  1.65K  [0402]
R618  10K  [0402]
R619  10K  [0402]
R623  10K  [0402]
R625  0  [0402]
R627  10K  [0402]
U64  IR3475  [qfn_supirbuck_4x5]
U65  IR3473  [qfn_supirbuck_4x5]
U66  IR3473  [qfn_supirbuck_4x5]
U67  IR3473  [qfn_supirbuck_4x5]
U68  IR3475  [qfn_supirbuck_4x5]
U69  IR3473  [qfn_supirbuck_4x5]
sheet 34 Other Pwr 2
C991  10uF  [0603]
C992  10uF  [0603]
C995  4.7uF  [0603]
C996  0.1uF  [0402]
C997  1uF  [0402]
C998  22uF  [0805]
C999  22uF  [0805]
C1004  1000pF  [0402]
C1005  10uF  [0603]
C1006  0.1uF  [0402]
C1007  10uF  [0603]
C1008  0.1uF  [0402]
C1009  1uF  [0402]
C1010  1uF  [0402]
C1011  1500pF  [0402]
C1012  10uF  [0603]
C1013  0.1uF  [0402]
C1014  NFM21PC225B0J3  [nfm21]
C1015  1uF  [0402]
C1016  1uF  [0402]
C1017  10uF  [0603]
C1018  0.1uF  [0402]
C1019  47uF  [0805]
C1020  0.1uF  [0402]
C1021  0.1uF  [0402]
C1022  0.1uF  [0402]
C1023  0.1uF  [0402]
C1024  0.1uF  [0402]
R631  10  [0402]
R636  1K  [0402]
R640  1K  [0402]
R641  100K  [0402]
R642  10K  [0402]
R643  4.32K  [0402]
R644  39.2K  [0402]
R645  10K  [0402]
R646  10K  [0402]
R647  36.5K  [0402]
R648  10K  [0402]
R649  9.31K  [0402]
R650  10K  [0402]
R651  10K  [0402]
U72  TPS51200  [dfn_p050_d040_b300_10_e240x165]
U73  MIC47100YMME  [msop_8_e170]
U74  TPS73701_SOT223  [sot223_5]
U75  MIC47100YMME  [msop_8_e170]

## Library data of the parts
C737-C741 C744-C750 C753-C757 C765-C770 C778-C780 C782-C788 C790-C796 C798 C801 C803 C806 C808 C811 C812 C815 C818-C821 C828-C833 C837-C845 C847 C853 C856-C859 C862 C864 C867 C870 C871 C878 C886 C889-C898 C902 C905 C907 C908 C919-C927 C930 C934 C936-C938 C948 C949 C952-C954 C960 C961 C966 C968 C996 C1006 C1008 C1013 C1018 C1020-C1024 = CAP: VOLTAGE: 16V
C742 C743 C751 C752 C764 C777 C781 C789 C800 C805 C810 C814 C822 C826 C834 C836 C850 C851 C854 C875 C876 C885 C887 C888 C901 C903 C904 C906 C911 C913-C915 C917 C918 C931-C933 C935 C941 C943-C945 C947 C950 C951 C964 C967 C974 C976 C977 C991 C992 C995 C997-C999 C1005 C1007 C1009 C1010 C1012 C1015-C1017 C1019 = CAP: VOLTAGE: 6.3V
C758 = CAP_E: TYPE: CAP; VOLTAGE: 25V
C759-C763 C771-C776 C799 C804 C809 C813 C823 C827 C835 C855 C912 C916 C942 C946 C975 = CAP: VOLTAGE: 25V
J26 = PCIE_X1: MPN: 87715-9001; TYPE: CON; Vendor: MOLEX
J27 J28 = MINIPCIE_CONN: MPN: 0717A01A68C; TYPE: CON; Vendor: CONCRAFT
J29 = SATA_CONN: MPN: 97-0901HB-7W-R; TYPE: CON; Vendor: Astron
M2-M5 = MH: MPN: 071CAAAZ68B; TYPE: CON; Vendor: CONCRAFT
R442-R485 R487 R489 R491-R498 R500 R501 R504 R506-R508 R511 R514 R515 R518 R519 R522 R524 R525 R528 R532 R533 R538-R542 R544 R545 R548 R549 R551-R556 R565 R568 R572 R581 R583 R585 R589 R590 R598 R601 R604 R607 R608 R618 R625 R631 R641 R642 R645 R648 R650 R708 R709 = RES: TOL: 5%
Z17 Z18 = MH: TYPE: PAD
J30 = CONN_2X35: CON 2X35 SKT SMT 0.8MM SP W/ LATCH 220H -; AGILE_PN: 211-78523; CAD_APPROVED: Yes; HEIGHT: 5.59 MM; MFG_NAME01: Samtec; MFG_PN01: ASP-135029-01; MPN: ASP-135029-01; ROHS: Yes; TYPE: CON; Vendor: Semtec
TP19 = TP: TYPE: PAD
J31 = CONN_2X5: MPN: TSW-105-07-F-D; TYPE: HDR; Vendor: Samtec
SW3 = SWITCH_DIP_8: MPN: DHNF-08F-V; TYPE: CON; Vendor: DIPTRONICS
U57 = EPM570F256: MPN: EPM570GF256C5N; TYPE: IC; Vendor: Altera
C797 C802 C807 = CAP: BOM_IGNORE: DNP; VOLTAGE: 50V
C816 C817 C824 C825 C852 C880 C909 C910 C939 C940 C972 C1004 C1011 = CAP: VOLTAGE: 50V
FB37-FB43 = BEAD: Vendor: Murata
R486 R488 R490 R523 R543 R570 R579 R587 R588 R596 R605 R606 R615 R623 = RES: BOM_IGNORE: DNP; TOL: 5%
U58 = ICS843004-01: MPN: 843004AG-01LF; TYPE: IC; Vendor: IDT
X1-X3 = OSC: MPN: 5x7mm,1.8V,+/-50ppm
X4 = OSC: MPN: KK3270021; Vendor: PERICOM
Y7 Y8 = CRYSTAL_4PIN: MPN: 3.2x2.5mm,+/-20ppm; TYPE: XTAL
R499 R502 R503 R505 R509 R512 R513 R516 R517 R520 R521 R527 = RES: BOM_IGNORE: DNP; TOL: 1%
U79 = IDT9FGV0641: MPN: 9FGV0641AKLF; TYPE: IC; Vendor: IDT
C846 C865 = CAP: BOM_IGNORE: DNP; VOLTAGE: 6.3V
C848 C849 = CAP_E: MPN: 2R5TPE470M7; TYPE: CAP; VOLTAGE: 2.5V; Vendor: SANYO
L7 = IND_IRON: MPN: IHLP4040DZER1R0M01; TYPE: IND; Vendor: Vishay
Q7 = NMOS_SO8FL: MPN: IRFH6200TRPBF; TYPE: MOS; Vendor: IR
Q8 = NMOS: MPN: IRLML6346TRPBF; TYPE: MOS; Vendor: IR
R534 = RES_PWR: MPN: WSL27261L000FEA; TYPE: RES; Vendor: Vishay
R535-R537 R546 R547 R550 R558 R564 R566 R567 R574-R578 R580 R582 R584 R586 R591-R595 R597 R599 R600 R602 R603 R609-R611 R613 R616 R619 R627 R636 R640 R643 R644 R646 R647 R649 R651 = RES: TOL: 1%
U60 U64 U68 = IR3475: MPN: IR3475MTR1PBF; TYPE: IC; Vendor: IR
U61 = 74CBTLV1G125: MPN: SN74CBTLV1G125DCKR; TYPE: IC; Vendor: TI
U62 = INA220: MPN: INA220AIDGST; TYPE: IC; Vendor: TI
C899 C900 C928 C929 C957 = CAP: BOM_IGNORE: DNP; VOLTAGE: 25V
L9 L13 L15 = IND_IRON: MPN: IHLP2525CZER2R2M01; TYPE: IND; Vendor: Vishay
L10 L11 = IND_IRON: MPN: IHLP2525CZER3R3M01; TYPE: IND; Vendor: Vishay
L12 = IND_IRON: MPN: IHLP2525CZER4R7M01; TYPE: IND; Vendor: Vishay
U65-U67 U69 = IR3475: MPN: IR3473MTR1PBF; TYPE: IC; Vendor: IR
C1014 = CAP_3T_4P: TYPE: CAP; Vendor: Murata
U72 = TPS51200: MPN: TPS51200DRCT; TYPE: IC; Vendor: TI
U73 U75 = MIC47100-MSOP8: MPN: MIC49150YMM; TYPE: IC; Vendor: Micrel
U74 = TPS73701_SOT223: MPN: TPS73701DCQ; TYPE: IC; Vendor: TI

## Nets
1V0: C964.1 C966.1 C967.1 C968.1 C976.1 C977.1 L15.2 R619.2 ; also on sheet 24 25
1V0S: C1012.1 C1013.1 R643.2 U73.7(OUT) U73.8(OUT) ; also on sheet 12
1V2_SLP: C871.1 C875.1 C876.1 C878.1 C887.1 C888.1 C991.1 C992.1 L9.2 R567.2 R636.2 U72.2(VLDOIN) ; also on sheet 3 13 35
1V5: C751.1 C752.1 C753.1 C754.1 C755.1 C756.1 C902.1 C903.1 C904.1 C905.1 C913.1 C914.1 J27.6(1.5V) J27.28(1.5V) J27.48(1.5V) J28.6(1.5V) J28.28(1.5V) J28.48(1.5V) L10.2 R582.2
1V8: C803.1 C804.1 FB38.1 R476.1 R478.1 R480.1 R482.1 ; also on sheet 4 5 7 12 13 35
1V8_0641_VDD: C836.1 C837.1 C838.1 FB43.2 R532.1 R533.1 U79.16(VDD1.8) U79.31(VDD1.8)
1V8_0641_VDDA: C834.1 C835.1 R533.2 U79.26(VDDA1.8)
1V8_0641_VDDIO: C828.1 C829.1 C830.1 C831.1 C832.1 C833.1 FB42.1 U79.5(VDDREF1.8) U79.12(VDDIO) U79.17(VDDIO) U79.27(VDDIO) U79.32(VDDIO) U79.39(VDDIO)
1V8_0641_VDDXTAL: C826.1 C827.1 R532.2 U79.4(VDDXTAL1.8)
1V8_OSC_DDR: C805.1 C806.1 FB38.2 X2.4(VDD)
1V8_OSC_SYS: C800.1 C801.1 FB37.2 X1.4(VDD)
1V8_OSC_USB: C810.1 C811.1 FB39.2 X3.4(VDD)
1V8_SLP: C777.1 C778.1 C779.1 C780.1 C789.1 C790.1 C791.1 C792.1 C793.1 C794.1 C795.1 C796.1 C798.1 C799.1 C808.1 C809.1 C839.1 C901.1 C906.1 C907.1 C908.1 C917.1 C918.1 C1009.1 C1015.1 FB37.1 FB39.1 FB42.2 FB43.1 L11.2 R508.1 R523.1 R525.1 R586.2 U57.A3(VCCIO2) U57.A14(VCCIO2) U57.C16(VCCIO2) U57.F8(VCCIO2) U57.F9(VCCIO2) U57.H8(VCCINT) U57.H10(VCCINT) U57.H11(VCCIO2) U57.J7(VCCINT) U57.J9(VCCINT) U57.J11(VCCIO2) U57.P16(VCCIO2) U73.1(IN) U73.2(IN) U75.1(IN) U75.2(IN) U79.11(VDDDIG1.8) ; also on sheet 7 12 13 35
1V35X: C1017.1 C1018.1 R649.2 U75.7(OUT) U75.8(OUT) ; also on sheet 12 13
2V5_SLP: C931.1 C932.1 C934.1 C937.1 C943.1 C944.1 L12.2 R602.2 ; also on sheet 7 8 12 19 35
2V5_VPP: C1007.1 C1008.1 C1011.2 C1014.1 R644.2 U74.2(OUT)
3V3: C742.1 C743.1 C744.1 C745.1 C746.1 C747.1 C764.1 C765.1 C766.1 C767.1 C818.1 C819.1 FB41.1 J26.A9(+3V3) J26.A10(+3V3) J26.B8(+3V3) J26.B10(+3V3AUX) J27.2(3.3V) J27.24(3.3VAUX) J27.52(3.3V) J28.2(3.3V) J28.24(3.3VAUX) J28.52(3.3V) R442.2 R443.2 R445.2 R446.2 R448.2 R449.2 R450.2 R451.2 R452.2 R453.2 R454.2 R455.2 R493.1 R498.1 U58.11(VCC) U58.18(VCC) ; also on sheet 5 6 7 9 11 12 14 15 16 17 18 20 21 22 23 35
3V3_OSC_CPLD: C814.1 C815.1 FB40.2 R491.1 X4.4(VDD)
3V3_PGOOD: R604.2 U57.L1(IO_B1) U68.3(PGOOD)
3V3_SLP: C781.1 C782.1 C783.1 C784.1 C785.1 C786.1 C787.1 C788.1 C812.1 C813.1 C856.1 C858.1 C933.1 C935.1 C936.1 C938.1 C947.1 C950.1 C951.1 C995.1 C1005.1 C1006.1 C1010.1 C1016.1 FB40.1 J31.4 L13.2 R456.2 R457.2 R458.2 R459.2 R460.2 R461.2 R462.2 R463.2 R464.2 R465.2 R466.2 R471.1 R472.1 R538.1 R539.1 R565.1 R568.1 R600.2 R604.1 R641.2 R642.2 R645.2 R648.2 R650.2 U57.C1(VCCIO1) U57.H6(VCCIO1) U57.J6(VCCIO1) U57.L8(VCCIO1) U57.L9(VCCIO1) U57.P1(VCCIO1) U57.T3(VCCIO1) U57.T14(VCCIO1) U61.5(VCC) U62.6(VS) U72.10(VIN) U73.4(BIAS) U74.1(IN) U75.4(BIAS) ; also on sheet 3 7 10 12 14 19 35 36
3V3A_843004: C822.1 C823.1 R498.2 U58.9(VCCA)
3V3O_843004: C820.1 C821.1 FB41.2 U58.3(VCCO) U58.22(VCCO)
5V0_SLP: C841.1 C842.1 C843.1 C844.1 C845.1 C859.2 C862.2 C864.1 C870.1 C889.1 C891.2 C892.2 C893.2 C894.1 C895.1 C897.2 C898.1 C920.2 C921.2 C922.1 C923.1 C924.1 C925.2 C926.2 C927.1 C948.1 C949.1 C952.2 C954.2 C960.1 C961.1 R535.1 R558.1 R575.1 R576.1 R579.1 R581.1 R583.1 R585.1 R593.1 R594.1 R596.1 R598.1 R601.1 R611.1 R615.1 R618.1 U60.10(VCC) U60.13(VIN) U64.10(VCC) U64.13(VIN) U65.10(VCC) U65.13(VIN) U66.10(VCC) U66.13(VIN) U67.10(VCC) U67.13(VIN) U68.10(VCC) U68.13(VIN) U69.10(VCC) U69.13(VIN) ; also on sheet 10 35 36
12V: C758.1 C759.1 C760.1 C761.1 C762.1 C763.1 J26.A2(+12V) J26.A3(+12V) J26.B1(+12V) J26.B2(+12V) J26.B3(+12V) ; also on sheet 15 17 35 36
12V_SLP: R549.2 ; also on sheet 35 36
GND: C742.2 C743.2 C744.2 C745.2 C746.2 C747.2 C751.2 C752.2 C753.2 C754.2 C755.2 C756.2 C758.2 C759.2 C760.2 C761.2 C762.2 C763.2 C764.2 C765.2 C766.2 C767.2 C777.2 C778.2 C779.2 C780.2 C781.2 C782.2 C783.2 C784.2 C785.2 C786.2 C787.2 C788.2 C789.2 C790.2 C791.2 C792.2 C793.2 C794.2 C795.2 C796.2 C797.2 C798.2 C799.2 C800.2 C801.2 C802.2 C803.2 C804.2 C805.2 C806.2 C807.2 C808.2 C809.2 C810.2 C811.2 C812.2 C813.2 C814.2 C815.2 C816.2 C817.2 C818.2 C819.2 C820.2 C821.2 C822.2 C823.2 C824.2 C825.2 C826.2 C827.2 C828.2 C829.2 C830.2 C831.2 C832.2 C833.2 C834.2 C835.2 C836.2 C837.2 C838.2 C839.2 C841.2 C842.2 C843.2 C844.2 C845.2 C846.1 C848.2 C849.2 C850.2 C851.2 C854.2 C855.2 C856.2 C857.2 C858.2 C859.1 C862.1 C864.2 C865.1 C870.2 C871.2 C875.2 C876.2 C885.2 C886.2 C887.2 C888.2 C889.2 C891.1 C892.1 C893.1 C894.2 C895.2 C897.1 C898.2 C899.1 C900.1 C901.2 C903.2 C904.2 C905.2 C906.2 C907.2 C911.2 C912.2 C913.2 C914.2 C915.2 C916.2 C917.2 C918.2 C920.1 C921.1 C922.2 C923.2 C924.2 C925.1 C926.1 C927.2 C928.1 C929.1 C931.2 C932.2 C933.2 C934.2 C935.2 C936.2 C941.2 C942.2 C943.2 C944.2 C945.2 C946.2 C947.2 C948.2 C949.2 C950.2 C951.2 C952.1 C954.1 C957.1 C960.2 C961.2 C964.2 C967.2 C968.2 C974.2 C975.2 C976.2 C977.2 C991.2 C992.2 C995.2 C996.2 C997.2 C998.2 C999.2 C1004.2 C1005.2 C1006.2 C1007.2 C1008.2 C1009.2 C1010.2 C1012.2 C1013.2 C1014.3 C1014.4 C1015.2 C1016.2 C1017.2 C1018.2 C1019.2 C1020.2 C1021.2 C1022.2 C1023.2 C1024.2 J26.A1(~{PRSNT1}) J26.A4(GND) J26.A12(GND) J26.A15(GND) J26.A18(GND) J26.B4(GND) J26.B7(GND) J26.B13(GND) J26.B16(GND) J26.B18(GND) J27.4(GND) J27.9(GND) J27.15(GND) J27.18(GND) J27.21(GND) J27.26(GND) J27.27(GND) J27.29(GND) J27.34(GND) J27.35(GND) J27.40(GND) J27.50(GND) J27.53(MS1) J27.54(MS2) J28.4(GND) J28.9(GND) J28.15(GND) J28.18(GND) J28.21(GND) J28.26(GND) J28.27(GND) J28.29(GND) J28.34(GND) J28.35(GND) J28.40(GND) J28.50(GND) J28.53(MS1) J28.54(MS2) J29.1(GND) J29.4(GND) J29.7(GND) J29.8(MH1) J29.9(MH2) J30.5(GND1) J30.11(GND2) J30.17(GND3) J30.23(GND4) J30.24(GND5) J30.29(GND6) J30.30(GND7) J30.35(GND8) J30.36(GND9) J30.41(GND10) J30.42(GND11) J30.47(GND12) J30.48(GND13) J30.53(GND14) J30.54(GND15) J30.59(GND16) J30.60(GND17) J30.65(GND18) J30.66(GND19) J30.G1(GND20) J30.G2(GND21) J31.2 J31.10 M2.1 M3.1 M4.1 M5.1 Q8.2(S) R444.2 R447.2 R470.1 R473.2 R474.2 R475.2 R477.2 R479.2 R481.2 R483.2 R485.1 R486.1 R488.1 R490.1 R494.1 R495.1 R496.1 R497.1 R499.2 R502.2 R503.1 R505.2 R509.1 R512.1 R513.2 R516.2 R517.1 R520.2 R521.1 R527.1 R528.1 R540.1 R545.1 R546.1 R553.1 R554.1 R555.1 R572.1 R574.1 R589.1 R590.1 R591.1 R592.1 R607.1 R608.1 R609.1 R610.1 R625.1 R627.1 R640.1 R646.1 R647.1 R651.1 R708.1 R709.1 SW3.9 U57.A1(GNDIO) U57.A16(GNDIO) U57.B2(GNDIO) U57.B15(GNDIO) U57.G7(GNDIO) U57.G8(GNDIO) U57.G9(GNDIO) U57.G10(GNDIO) U57.H7(GNDINT) U57.H9(GNDINT) U57.J8(GNDINT) U57.J10(GNDINT) U57.K7(GNDIO) U57.K8(GNDIO) U57.K9(GNDIO) U57.K10(GNDIO) U57.R2(GNDIO) U57.R15(GNDIO) U57.T1(GNDIO) U57.T16(GNDIO) U58.15(GND) U58.19(GND) U60.4(GND) U60.11(PGND) U60.17(GND) U61.3(GND) U62.7(GND) U64.4(GND) U64.11(PGND) U64.17(GND) U65.4(GND) U65.11(PGND) U65.17(GND) U66.4(GND) U66.11(PGND) U66.17(GND) U67.4(GND) U67.11(PGND) U67.17(GND) U68.4(GND) U68.11(PGND) U68.17(GND) U69.4(GND) U69.11(PGND) U69.17(GND) U72.4(PGND) U72.8(GND) U72.11(PAD) U73.3(GND) U73.9(EPAD) U74.3(GND) U74.6(GND(TAB)) U75.3(GND) U75.9(EPAD) U79.8(GNDDIG) U79.41(EPAD) X1.2(GND) X2.2(GND) X3.2(GND) X4.2(GND) Y7.2 Y7.4 Y8.2 Y8.4 Z17.1 Z18.1 ; also on sheet 3 4 5 6 7 8 9 10 11 12 13 14 15 16 17 18 19 20 21 22 23 24 25 26 35 36 37
SVDD_EN: R645.1 U57.T12(IO_B1) U73.5(EN)
VDD_EN_N: R552.1 U57.N12(IO_B1)
AURORA_CLKOUT: J30.20(I/O_3) R462.1
AURORA_EVTI_N: R468.1 U57.R8(IO_B1)
AURORA_EVTO_N: R469.1 U57.T8(IO_B1)
AURORA_HALT_N: R467.1 U57.T7(IO_B1)
AURORA_HRST_N: J30.34(I/O_5) R461.1 U57.P9(IO_B1)
AURORA_PORST_N: J30.22(RESET) R460.1 U57.T9(IO_B1)
AURORA_RDY_N: J30.32(I/O_4) TP19.1(TP)
AURORA_REFCLK_N: J30.28(CLK_N) R504.2 R512.2
AURORA_REFCLK_P: J30.26(CLK_P) R503.2 R511.2
AURORA_RX_N: C776.2 ; also on sheet 9
AURORA_RX_P: C775.2 ; also on sheet 9
AURORA_TCK: J30.4(TCK) R459.1 U57.R5(IO_B1)
AURORA_TDI: J30.8(TDI) R457.1 U57.T5(IO_B1)
AURORA_TDO: J30.10(TDO) U57.R7(IO_B1)
AURORA_TMS: J30.6(TMS) R458.1 U57.T6(IO_B1)
AURORA_TRST_N: J30.12(TRST) R456.1 U57.R6(IO_B1)
AURORA_TX_N: J30.3(TX0_N) ; also on sheet 9
AURORA_TX_P: J30.1(TX0_P) ; also on sheet 9
BOOT_FLASH_SEL: R476.2 SW3.4 U57.F15(IO_B2)
CFG_VBANK0: R478.2 SW3.5 U57.J16(IO_B2) ; also on sheet 5
CFG_VBANK1: R480.2 SW3.6 U57.H16(IO_B2) ; also on sheet 5
CFG_VBANK2: R482.2 SW3.7 U57.J15(IO_B2) ; also on sheet 5
CKE_ISO_EN: U57.G3(IO_B1) ; also on sheet 35
CKSTP_OUT_N: U57.C9(IO_B2) ; also on sheet 7
COP_CKSTP_OUT_N: U57.G1(IO_B1) ; also on sheet 7
COP_HRESET_N: U57.G2(IO_B1) ; also on sheet 7
COP_SRESET_N: U57.F1(IO_B1) ; also on sheet 7
COP_TCK: U57.E1(IO_B1) ; also on sheet 7
COP_TDI: U57.E2(IO_B1) ; also on sheet 7
COP_TDO: U57.D2(IO_B1) ; also on sheet 7
COP_TMS: U57.F2(IO_B1) ; also on sheet 7
COP_TRST_N: U57.D1(IO_B1) ; also on sheet 7
CPLD_INT1_N: U57.C15(IO_B2) ; also on sheet 7
CPLD_INT2_N: U57.D14(IO_B2) ; also on sheet 7
CPLD_REFCLK: R492.2 U57.H5(GCLK0p)
CPLD_TCK: J31.1 R470.2 U57.P3(TCK)
CPLD_TDI: J31.9 R472.2 U57.L6(TDI)
CPLD_TDO: J31.3 U57.M5(TDO)
CPLD_TMS: J31.5 R471.2 U57.N4(TMS)
DDR_PGOOD: R568.2 U57.T10(IO_B1) U64.3(PGOOD)
DDR_REFCLK: R487.2 R488.2 ; also on sheet 7
DDR_RST_N: U57.A2(IO_B2) ; also on sheet 3
DDRPWR_EN: C865.2 R565.2 U57.R9(IO_B1) U64.16(EN)
DFP_BACKLIGHT: U57.J1(IO_B1) ; also on sheet 17
DFP_BL_PWM: U57.K1(IO_B1) ; also on sheet 17
DFP_INT_N: U57.P6(IO_B1) ; also on sheet 17
DFP_MODE: U57.R4(IO_B1) ; also on sheet 17
DFP_RST_N: U57.N5(IO_B1) ; also on sheet 17
DVI_INT_N: U57.L2(IO_B1) ; also on sheet 16
DVI_RST_N: U57.M1(IO_B1) ; also on sheet 16
EC1_RST_N: U57.M2(IO_B1) ; also on sheet 19
EC2_RST_N: U57.N1(IO_B1) ; also on sheet 20
EVDD_SEL: U57.C2(IO_B1) ; also on sheet 35
EVT0_N: U57.E13(IO_B2) ; also on sheet 7
EVT1_N: U57.F13(IO_B2) ; also on sheet 7
EVT4_N: U57.B14(IO_B2) ; also on sheet 7
EVT_BRD_ISO: U57.K16(IO_B2) ; also on sheet 7
EVT_PWR_EN: U57.L15(IO_B2) ; also on sheet 7
EVT_PWR_OK: U57.L16(IO_B2) ; also on sheet 7
FAN_PWM: U57.R16(IO_B1) ; also on sheet 36
FAN_TACH: U57.T15(IO_B1) ; also on sheet 36
GPIO_CKE_ISO: U57.P7(IO_B1) ; also on sheet 7
GVDD_EN_N: U57.T11(IO_B1) ; also on sheet 35
HRESET_N: U57.F14(IO_B2) ; also on sheet 7
I2C1_SCL_SLP: U62.5(SCL) U79.9(SCLK_3.3) ; also on sheet 3 7 14
I2C1_SDA_SLP: U62.4(SDA) U79.10(SDATA_3.3) ; also on sheet 3 7 14
I2C2_MPEX1_SCL: J27.30(SMB_CLK) R442.1 ; also on sheet 7
I2C2_MPEX1_SDA: J27.32(SMB_DATA) R443.1 ; also on sheet 7
I2C2_MPEX2_SCL: J28.30(SMB_CLK) R453.1 ; also on sheet 7
I2C2_MPEX2_SDA: J28.32(SMB_DATA) R454.1 ; also on sheet 7
I2C2_PEX_SCL: J26.B5(SMCLK) R450.1 ; also on sheet 7
I2C2_PEX_SDA: J26.B6(SMDAT) R451.1 ; also on sheet 7
IFC_A16: U57.D16(IO_B2) ; also on sheet 4 5
IFC_A17: U57.E15(IO_B2) ; also on sheet 4 5
IFC_A27: U57.C13(IO_B2) ; also on sheet 4 5
IFC_A28: U57.C12(IO_B2) ; also on sheet 4 5
IFC_A29: U57.C11(IO_B2) ; also on sheet 4 5
IFC_A30: U57.D12(IO_B2) ; also on sheet 4 5
IFC_A31: U57.A5(IO_B2) ; also on sheet 4
IFC_AD0: U57.A13(IO_B2) ; also on sheet 4 5
IFC_AD1: U57.B13(IO_B2) ; also on sheet 4 5
IFC_AD2: U57.B12(IO_B2) ; also on sheet 4 5
IFC_AD3: U57.A12(IO_B2) ; also on sheet 4 5
IFC_AD4: U57.A11(IO_B2) ; also on sheet 4 5
IFC_AD5: U57.B11(IO_B2) ; also on sheet 4 5
IFC_AD6: U57.B10(IO_B2) ; also on sheet 4 5
IFC_AD7: U57.A10(IO_B2) ; also on sheet 4 5
IFC_AD8: U57.A6(IO_B2) ; also on sheet 4 5
IFC_AD9: U57.B7(IO_B2) ; also on sheet 4 5
IFC_AD10: U57.A7(IO_B2) ; also on sheet 4 5
IFC_AD11: U57.B8(IO_B2) ; also on sheet 4 5
IFC_AD12: U57.A8(IO_B2) ; also on sheet 4 5
IFC_AD13: U57.C8(IO_B2) ; also on sheet 4 5
IFC_AD14: U57.A9(IO_B2) ; also on sheet 4 5
IFC_AD15: U57.B9(IO_B2) ; also on sheet 4 5
IFC_CLE: U57.D15(IO_B2) ; also on sheet 4 5
IFC_CLK: U57.J12(GCLK2p) ; also on sheet 4
IFC_CS0_N: U57.B6(IO_B2) ; also on sheet 4
IFC_CS1_N: U57.B5(IO_B2) ; also on sheet 4
IFC_CS2_N: U57.A4(IO_B2) ; also on sheet 4
IFC_OE_N: SW3.2 U57.G15(IO_B2) ; also on sheet 4 5
IFC_RB0_N: U57.A15(IO_B2) ; also on sheet 4
IFC_RB1_N: U57.B16(IO_B2) ; also on sheet 4
IFC_WE_N: SW3.1 U57.H15(IO_B2) ; also on sheet 4 5
IFC_WP_N: SW3.3 U57.F16(IO_B2) ; also on sheet 4 5
INA_VCORE_N: C853.2 R542.1 U62.9(VIN-)
INA_VCORE_P: C853.1 R541.1 U62.10(VIN+)
IO_B1: U57.B1(IO_B2)
IO_B3: U57.B3(IO_B2)
IO_D4: U57.D4(IO_B2)
IO_D5: U57.D5(IO_B2)
IO_G14: U57.G14(IO_B2)
IO_H14: U57.H14(IO_B2)
IO_J14: U57.J14(IO_B2)
IO_K14: U57.K14(IO_B2)
IO_L13: U57.L13(IO_B2)
IO_L14: U57.L14(IO_B2)
IO_M13: U57.M13(IO_B2)
IO_M14: U57.M14(IO_B2)
IO_M15: U57.M15(IO_B2)
IO_N13: U57.N13(IO_B2)
IO_N14: U57.N14(IO_B2)
IO_N15: U57.N15(IO_B2)
IO_N16: U57.N16(IO_B2)
IOPWR_EN: C899.2 C957.2 R579.2 R615.2 U57.K2(IO_B1) U66.16(EN) U69.16(EN) ; also on sheet 35
IOPWR_EN_N: U57.T2(IO_B1) ; also on sheet 35
JTAG_TCK: U57.B4(IO_B2) ; also on sheet 7
JTAG_TDI: U57.C4(IO_B2) ; also on sheet 7
JTAG_TDO: U57.C6(IO_B2) ; also on sheet 7
JTAG_TMS: U57.C5(IO_B2) ; also on sheet 7
JTAG_TRST_N: U57.C7(IO_B2) ; also on sheet 7
LED_STATUS: U57.H2(IO_B1) ; also on sheet 36
MPEX1_REFCLK_N: J27.13(REFCLK+) R507.2 R513.1
MPEX1_REFCLK_P: J27.11(REFCLK-) R505.1 R506.2
MPEX1_RST_N: J27.22(~{PERST}) U57.E4(IO_B1)
MPEX1_RX_N: C738.2 ; also on sheet 8
MPEX1_RX_P: C737.2 ; also on sheet 8
MPEX1_TX_N: C740.2 ; also on sheet 8
MPEX1_TX_P: C739.2 ; also on sheet 8
MPEX2_REFCLK_N: J28.13(REFCLK+) R515.2 R517.2
MPEX2_REFCLK_P: J28.11(REFCLK-) R509.2 R514.2
MPEX2_RST_N: J28.22(~{PERST}) U57.E3(IO_B1)
MPEX2_RX_N: C768.2 ; also on sheet 8
MPEX2_RX_P: C757.2 ; also on sheet 8
MPEX2_TX_N: C770.2 ; also on sheet 8
MPEX2_TX_P: C769.2 ; also on sheet 8
MVREF: C996.1 U72.6(REFOUT) ; also on sheet 3
NAND_CS_N: U57.G16(IO_B2) ; also on sheet 5
NAND_RB_N: U57.D11(IO_B2) ; also on sheet 5
NOR_CS_N: U57.D13(IO_B2) ; also on sheet 5
NOR_RB_N: U57.E14(IO_B2) ; also on sheet 5
NOR_RST_N: U57.C14(IO_B2) ; also on sheet 5
PEX_PRS_N: J26.B17(~{PRSNT2}_X1) R449.1 U57.P5(IO_B1)
PEX_REFCLK_N: J26.A14(REFCLK-) R501.2 R502.1
PEX_REFCLK_P: J26.A13(REFCLK+) R499.1 R500.2
PEX_RST_N: J26.A11(~{PERST}) U57.M4(IO_B1)
PEX_RX_N: C748.2 ; also on sheet 9
PEX_RX_P: C741.2 ; also on sheet 9
PEX_SEL: U57.T4(IO_B1) ; also on sheet 9
PEX_TX_N: C750.2 ; also on sheet 9
PEX_TX_P: C749.2 ; also on sheet 9
PORESET_N: U57.C10(IO_B2) ; also on sheet 7
PROFI_MUX_CFG: U57.R13(IO_B1) ; also on sheet 18
PWR_GOOD: U57.H1(IO_B1) ; also on sheet 36
PWR_RST_N: U57.J2(IO_B1) ; also on sheet 36
QE_MUX_CFG0: U57.T13(IO_B1) ; also on sheet 11
QE_MUX_CFG1: U57.R12(IO_B1) ; also on sheet 11
QSG1_INT_N: U57.K3(IO_B1) ; also on sheet 24
QSG1_REFCLK_N: R497.2 U58.4(Q0) ; also on sheet 24
QSG1_REFCLK_P: R496.2 U58.5(~{Q0}) ; also on sheet 24
QSG1_RST_N: U57.R1(IO_B1) ; also on sheet 24
QSG2_INT_N: U57.L3(IO_B1) ; also on sheet 25
QSG2_REFCLK_N: R709.2 U58.21(Q3) ; also on sheet 25
QSG2_REFCLK_P: R708.2 U58.20(~{Q3}) ; also on sheet 25
QSG2_RST_N: U57.M3(IO_B1) ; also on sheet 25
QSG_SEL_N: U57.L4(IO_B1) ; also on sheet 9
RESET_REQ_N: U57.K15(IO_B2) ; also on sheet 7
SATA_RX_N: C773.1 ; also on sheet 8
SATA_RX_P: C774.1 ; also on sheet 8
SATA_TX_N: C772.1 ; also on sheet 8
SATA_TX_P: C771.1 ; also on sheet 8
SD_REFCLK1_N: R519.2 R520.1 ; also on sheet 8
SD_REFCLK1_P: R516.1 R518.2 ; also on sheet 8
SD_REFCLK2_N: R494.2 U58.1(~{Q1}) ; also on sheet 8
SD_REFCLK2_P: R495.2 U58.2(Q1) ; also on sheet 8
SD_REFCLK_EN_N: R508.2 U57.P15(IO_B2) U79.13(~{OE0}) U79.21(~{OE1}) U79.24(~{OE2}) U79.30(~{OE3}) U79.35(~{OE4})
SDHC_VS: U57.M16(IO_B2) ; also on sheet 7
SENSEVDD: R551.1 ; also on sheet 12
SENSEVDD_EN_N: U57.H3(IO_B1) U61.1(~{OE})
SENSEVDDC: R550.1 ; also on sheet 12
SG1_INT_N: U57.P2(IO_B1) ; also on sheet 22
SG1_RST_N: U57.R3(IO_B1) ; also on sheet 22
SG2_INT_N: U57.N3(IO_B1) ; also on sheet 23
SG2_RST_N: U57.P4(IO_B1) ; also on sheet 23
SG_RST_N: U57.N2(IO_B1) ; also on sheet 21
SINGLE_CLK_EN_N: R485.2 U57.P14(IO_B2) U79.38(~{OE5}) X1.1(OE) X2.1(OE) X3.1(OE)
SYS_REFCLK: R484.2 R486.2 ; also on sheet 7
SYS_REFCLK_N: R524.2 R527.2 ; also on sheet 7
SYS_REFCLK_P: R521.2 R522.2 ; also on sheet 7
TDMR1_INT_N: U57.P11(IO_B1) ; also on sheet 15
TDMR2_INT_N: U57.P10(IO_B1) ; also on sheet 15
TDMR_PRS_N: U57.P12(IO_B1) ; also on sheet 15
TDMR_RST_N: U57.P8(IO_B1) ; also on sheet 15 18
TDMR_SLP_N: U57.R14(IO_B1) ; also on sheet 15
TEST_SEL_N: SW3.8 U57.E16(IO_B2) ; also on sheet 7
THERM_ALERT_N: U57.C3(IO_B1) ; also on sheet 14
THERM_FAULT_N: U57.F3(IO_B1) ; also on sheet 14
USB_REFCLK: R489.2 R490.2 ; also on sheet 10
VCORE: Q7.1 Q7.2 Q7.3 R540.2 ; also on sheet 12
VCORE_EN: C846.2 R538.2 U57.P13(IO_B1) U60.16(EN)
VCORE_PGOOD: R539.2 U57.J3(IO_B1) U60.3(PGOOD)
VCORE_SLP: Q7.5 R534.4 ; also on sheet 12
VPP: C1014.2 C1019.1 C1020.1 C1021.1 C1022.1 C1023.1 C1024.1 ; also on sheet 3
VPP_EN: R648.1 U57.R10(IO_B1) U74.5(EN)
VTT: C998.1 C999.1 R631.2 U72.3(VO) ; also on sheet 3
VTT_EN: R642.1 U57.D3(IO_B1) U72.7(EN)
XVDD_EN: R650.1 U57.R11(IO_B1) U75.5(EN)
N16984231: C739.1 J27.33(PETP0)
N16984233: C740.1 J27.31(PETN0)
N16984263: C737.1 J27.25(PERP0)
N16984265: C738.1 J27.23(PERN0)
N16985354: C769.1 J28.33(PETP0)
N16985356: C770.1 J28.31(PETN0)
N16985386: C757.1 J28.25(PERP0)
N16985388: C768.1 J28.23(PERN0)
N17111815: J27.1(~{WAKE}) R446.1
N17112169: J28.1(~{WAKE}) R455.1
N17170143: C797.1 R484.1 X1.3(OUT)
N17232338: C802.1 R487.1 X2.3(OUT)
N17249127: C748.1 J26.A17(PERN0)
N17249129: C741.1 J26.A16(PERP0)
N17249144: J26.B11(~{WAKE}) R452.1
N17249162: J26.A8(JTAG5_TMS) R445.1
N17249180: J26.B9(JTAG1_~{TRST}) R444.1
N17249182: J26.A5(JTAG2_TCK) R447.1
N17249192: J26.A6(JTAG3_TDI) R448.1
N17249250: C750.1 J26.B15(PETN0)
N17249252: C749.1 J26.B14(PETP0)
N17251651: C867.2 L9.1 R564.2 R566.1 U64.12(PHASE)
N17251653: C878.2 C880.2 R566.2
N17251663: C880.1 R567.1 R574.2 U64.5(FB)
N17251677: C885.1 R570.1 U64.8(3VCBP)
N17251680: R570.2 R572.2 U64.1(FCCM)
N17251691: C886.1 U64.6(SS)
N17251709: R558.2 U64.15(FF)
N17251715: C867.1 U64.14(BOOT)
N17251719: R564.1 U64.2(ISET)
N17251739: C890.2 L11.1 R578.2 R584.1 U65.12(PHASE)
N17251740: C908.2 C910.2 R584.2
N17251749: C910.1 R586.1 R592.2 U65.5(FB)
N17251753: R578.1 U65.2(ISET)
N17251755: R585.2 U65.3(PGOOD)
N17251758: C900.2 R583.2 U65.16(EN)
N17251765: C915.1 R588.1 U65.8(3VCBP)
N17251768: R588.2 R590.2 U65.1(FCCM)
N17251782: C916.1 U65.6(SS)
N17251797: R576.2 U65.15(FF)
N17251803: C890.1 U65.14(BOOT)
N17251826: C930.2 L13.1 R599.1 R603.2 U68.12(PHASE)
N17251827: C938.2 C940.2 R599.2
N17251836: C940.1 R600.1 R610.2 U68.5(FB)
N17251840: R603.1 U68.2(ISET)
N17251850: C929.2 R598.2 U68.16(EN)
N17251857: C945.1 R606.1 U68.8(3VCBP)
N17251860: R606.2 R608.2 U68.1(FCCM)
N17251871: C946.1 U68.6(SS)
N17251886: R594.2 U68.15(FF)
N17251892: C930.1 U68.14(BOOT)
N17251915: C919.2 L12.1 R595.2 R597.1 U67.12(PHASE)
N17251916: C937.2 C939.2 R597.2
N17251925: C939.1 R602.1 R609.2 U67.5(FB)
N17251929: R595.1 U67.2(ISET)
N17251934: R601.2 U67.3(PGOOD)
N17251937: C928.2 R596.2 U67.16(EN)
N17251944: C941.1 R605.1 U67.8(3VCBP)
N17251947: R605.2 R607.2 U67.1(FCCM)
N17251958: C942.1 U67.6(SS)
N17251973: R593.2 U67.15(FF)
N17251979: C919.1 U67.14(BOOT)
N17252002: C896.2 L10.1 R577.2 R580.1 U66.12(PHASE)
N17252003: C902.2 C909.2 R580.2
N17252012: C909.1 R582.1 R591.2 U66.5(FB)
N17252016: R577.1 U66.2(ISET)
N17252018: R581.2 U66.3(PGOOD)
N17252028: C911.1 R587.1 U66.8(3VCBP)
N17252031: R587.2 R589.2 U66.1(FCCM)
N17252042: C912.1 U66.6(SS)
N17252057: R575.2 U66.15(FF)
N17252063: C896.1 U66.14(BOOT)
N17526494: R535.2 U60.15(FF)
N17526498: C854.1 R543.1 U60.8(3VCBP)
N17526502: R543.2 R545.2 U60.1(FCCM)
N17526505: C840.2 L7.1 R536.2 R537.1 U60.12(PHASE)
N17526509: C847.1 C852.1 R537.2
N17526513: C847.2 C848.1 C849.1 C850.1 C851.1 L7.2 R534.1 R548.2
N17526517: C852.2 R546.2 R547.2 U60.5(FB)
N17526563: C855.1 U60.6(SS)
N17526565: C840.1 U60.14(BOOT)
N17526568: R536.1 U60.2(ISET)
N17526574: R551.2 U61.2(A)
N17526575: R547.1 R548.1 R550.2 R556.2 U61.4(B)
N17557626: C775.1 J30.13(RX0_P)
N17557628: C776.1 J30.15(RX0_N)
N17558733: J30.14(I/O_0) R465.1 R467.2
N17558754: J30.16(I/O_1) R464.1 R468.2
N17558775: J30.18(I/O_2) R463.1 R469.2
N17559329: J30.2(VIO) R466.1
N17609926: R643.1 R646.2 U73.6(FB/ADJ)
N17609966: C1004.1 R636.1 R640.2 U72.1(REFIN)
N17609980: C997.1 R631.1 U72.5(VOSNS)
N17610004: R641.1 U72.9(PGOOD)
N17612202: R649.1 R651.2 U75.6(FB/ADJ)
N17692970: C816.1 U58.14(XTAL_IN) Y7.1
N17692982: C817.1 U58.13(XTAL_OUT) Y7.3
N17693054: R493.2 U58.10(F_SEL0)
N17697384: C807.1 R489.1 X3.3(OUT)
N17708927: R492.1 X4.3(OUT)
N17708947: R491.2 X4.1(OE)
N17743915: C1011.1 R644.1 R647.2 U74.4(NR/FB)
N17947254: R525.2 U79.6(SADR/REF1.8)
N17947282: R523.2 R528.2 U79.1(SS_EN_TRI)
N17947998: C824.1 U79.2(X1_25) Y8.1
N17948004: C825.1 U79.3(X2) Y8.3
N17952438: R500.1 U79.14(DIF0)
N17952440: R501.1 U79.15(~{DIF0})
N17952563: R506.1 U79.22(DIF2)
N17952565: R507.1 U79.23(~{DIF2})
N17952567: R514.1 U79.28(DIF3)
N17952569: R515.1 U79.29(~{DIF3})
N17952583: R518.1 U79.33(DIF4)
N17952585: R519.1 U79.34(~{DIF4})
N17952595: R524.1 U79.37(~{DIF5})
N17952601: R522.1 U79.36(DIF5)
N17952605: R504.1 U79.19(~{DIF1})
N17952607: R511.1 U79.18(DIF1)
N18280039: C966.2 C972.2 R616.2
N18280045: C953.2 L15.1 R613.2 R616.1 U69.12(PHASE)
N18280055: R618.2 U69.3(PGOOD)
N18280059: R613.1 U69.2(ISET)
N18280061: C972.1 R619.1 R627.2 U69.5(FB)
N18280085: C974.1 R623.1 U69.8(3VCBP)
N18280087: R623.2 R625.2 U69.1(FCCM)
N18280133: C975.1 U69.6(SS)
N18280157: C953.1 U69.14(BOOT)
N18280169: R611.2 U69.15(FF)
N18382428: R473.1 SW3.16
N18394326: R474.1 SW3.15
N18394329: R475.1 SW3.14
N18394330: R477.1 SW3.13
N18394334: R481.1 SW3.11
N18394336: R483.1 SW3.10
N18629823: C772.2 J29.3(TX_N)
N18629826: C771.2 J29.2(TX_P)
N18629885: C773.2 J29.5(RX_N)
N18629888: C774.2 J29.6(RX_P)
N19126530: R479.1 SW3.12
N23926306: Q7.4 R544.2
N23926329: C857.1 Q8.3(D) R544.1 R549.1
N23926341: Q8.1(G) R552.2 R553.2
N23927707: R534.2 R541.2
N23927714: R534.3 R542.2
N23928633: R554.2 U62.2(A0)
N23928636: R555.2 U62.1(A1)
N23929117: R556.1 U62.8(VBUS)

Not connected (* = marked no-connect by the designer): J26 A7(JTAG4_TDO)* B12(RSVD1)*; J27 3(RSVD1)* 5(RSVD2)* 7(~{CLKREQ})* 8(RSVD3)* 10(RSVD4)* 12(RSVD5)* 14(RSVD6)* 16(RSVD7)* 17(RSVD8)* 19(RSVD9)* 20(RSVD10)* 36(USB_D-)* 37(RSVD11)* 38(USB_D+)* 39(RSVD12)* 41(RSVD13)* 42(~{LED_WWAN})* 43(RSVD14)* 44(~{LED_WLAN})* 45(RSVD15)* 46(~{LED_WPAN})* 47(RSVD16)* 49(RSVD17)* 51(RSVD18)*; J28 3(RSVD1)* 5(RSVD2)* 7(~{CLKREQ})* 8(RSVD3)* 10(RSVD4)* 12(RSVD5)* 14(RSVD6)* 16(RSVD7)* 17(RSVD8)* 19(RSVD9)* 20(RSVD10)* 36(USB_D-)* 37(RSVD11)* 38(USB_D+)* 39(RSVD12)* 41(RSVD13)* 42(~{LED_WWAN})* 43(RSVD14)* 44(~{LED_WLAN})* 45(RSVD15)* 46(~{LED_WPAN})* 47(RSVD16)* 49(RSVD17)* 51(RSVD18)*; J30 7(TX1_P)* 9(TX1_N)* 19(RX1_P)* 21(RX1_N)* 25(TX2_P)* 27(TX2_N)* 31(TX3_P)* 33(TX3_N)* 37(RX2_P)* 38(RSV1)* 39(RX2_N)* 40(RSV2)* 43(RX3_P)* 44(RSV3)* 45(RX3_N)* 46(RSV4)* 49(TX4_P)* 50(RSV5)* 51(TX4_N)* 52(RSV6)* 55(TX5_P)* 56(RSV7)* 57(TX5_N)* 58(RSV8)* 61(TX6_P)* 62(RSV9)* 63(TX6_N)* 64(RSV10)* 67(TX7_P)* 68(RSV11)* 69(TX7_N)* 70(RSV12)*; J31 6* 7* 8*; U57 D6(NC)* D7(NC)* D8(NC)* D9(NC)* D10(NC)* E5(NC)* E6(NC)* E7(NC)* E8(NC)* E9(NC)* E10(NC)* E11(NC)* E12(NC)* F4(NC)* F5(NC)* F6(NC)* F7(NC)* F10(NC)* F11(NC)* F12(NC)* G4(NC)* G5(NC)* G6(NC)* G11(NC)* G12(NC)* G13(NC)* H4(NC)* H12(GCLK3p)* H13(NC)* J4(NC)* J5(GCLK1p)* J13(NC)* K4(NC)* K5(NC)* K6(NC)* K11(NC)* K12(NC)* K13(NC)* L5(NC)* L7(NC)* L10(NC)* L11(NC)* L12(NC)* M6(NC)* M7(NC)* M8(DEV_OE)* M9(DEV_CLRn)* M10(NC)* M11(NC)* M12(NC)* N6(NC)* N7(NC)* N8(NC)* N9(NC)* N10(NC)* N11(NC)*; U58 6(MR)* 7(~{PLL_SEL})* 8(NC)* 12(F_SEL1)* 16(TEST_CLK)* 17(~{XTAL_SEL})* 23(Q2)* 24(~{Q2})*; U60 7(NC1)* 9(NC2)*; U62 3(NC)*; U64 7(NC1)* 9(NC2)*; U65 7(NC1)* 9(NC2)*; U66 7(NC1)* 9(NC2)*; U67 7(NC1)* 9(NC2)*; U68 7(NC1)* 9(NC2)*; U69 7(NC1)* 9(NC2)*; U79 7(NC1)* 20(NC2)* 25(NC3)* 40(~{CKPWRGD_PD})*

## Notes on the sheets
sheet 27
- PCIe X1 SLOT, MINI PCIe and SATA CONNECTORs
- MINI PCIe CONNECTOR
- PCIe x1 SLOT
- 100 ohms
  DIFF PAIRs
- 100 ohms
  DIFF PAIRs
- MINI PCIe CONNECTOR
- 100 ohms
  DIFF PAIRs
- ON-BOARD SATA CONNECTOR
- T1040 ONLY!
- 100 ohms
  DIFF PAIRs
sheet 28
- AURORA PORT
- 100 ohms
  DIFF PAIRs
- Aurora expects DC©\blocking caps at RX
- (OPEN-DRAIN)
- AURORA NET
- DUT PIN
- FUNCTION
- IO0
- AURORA_HALT_N
- EVT0_N
- POWER©\ON DEBUG INPUT FROM DCU TO DUT
- IO1
- AURORA_EVTI_N
- EVT1_N
- SYNC PACKET REQUEST FROM DCU TO DUT
- IO2
- AURORA_EVTO_N
- EVT4_N
- WATCHPOINT TRIG OUT FROM DUT TO DCU
- IO3
- AURORA_CLKOUT
- CLKOUT
- CLKOUT DEBUG CLKOUT FROM DUT TO DCU
- IO4
- IO5
- AURORA_RDY_N
- DUT_HRESET_N
- HRESET_N
- NA
- OPEN©\DRAIN WARM RESET TO/FROM DUT
- R/W ACCESS TRANSFER COMPLETE W/O ERROR
- 100 ohms
  DIFF PAIR
- (OPEN-DRAIN)
sheet 29
- CPLD
- 3.3V BANK1 IO
- 1.8V BANK2 IO
- cfg
- cfg
- cfg
- cfg
- cfg
- cfg
- cfg
- cfg
- OD OUTPUT
- OD OUTPUT
- cfg
- cfg
- cfg
- cfg
- cfg
- cfg
- OD OUTPUT
- OD OUTPUT
- cfg
- CPLD JTAG CONNECTOR
- cfg_eng_use0
- cfg_eng_use1
- cfg_eng_use2
sheet 30
- SYSTEM CLOCK GENERATORs
- 125MHz
sheet 31
- SYSTEM CLOCK GENERATORs (cont.)
- I2C ADDR = 0x6A
- Integrated output terminations providing Zo=100
- DEFAULT NO SPREAD
sheet 32
- T104X CORE POWER CONVERTOR
- Caution: separate analog and power ground and make connection at GND plane
- COPPER ISLAND
- COPPER PLANE
- Rff(kohm) = Vout/(1Vx20pFxFsw)
- 1.0uH(IHLP2525CZER1R0M01): Irms = 11A, Isat = 22A, DCR = 9mohm
- COPPER PLANE
- Fsw = 400KHz
- Vout = 0.5x(Rtop/Rbot+1)
- Rset = 13(mohm)xIoc/19(uA)
- DISCHARGE LOAD
- Enable DCM Mode
- Css(nF) = 22xTss(mS)
- I2C ADDR = 0x40
- 5~7 ohm on-state switch resistance
sheet 33
- SYSTEM POWER CONVERTORs
- 2.2uH(IHLP2525CZER2R2M01): Irms = 8A, Isat = 14A, DCR = 18mohm
- 3.3uH(IHLP2525CZER3R3M01): Irms = 6A, Isat = 13.5A, DCR = 28mohm
- COPPER ISLAND
- 4.7uH(IHLP2525CZER4R7M01): Irms = 5.5A, Isat = 10A, DCR = 37mohm
- COPPER ISLAND
- MAX 10A
- Rff(kohm) = Vout/(1Vx20pFxFsw)
- SWITCHABLE
- COPPER PLANE
- Rff(kohm) = Vout/(1Vx20pFxFsw)
- ALWAYS ON
- COPPER PLANE
- Fsw = 400KHz
- Rset = 24(mohm)xIoc/19(uA)
- Fsw = 400KHz
- Rset = 13(mohm)xIoc/19(uA)
- Vout = 0.5x(Rtop/Rbot+1)
- Vout = 0.5x(Rtop/Rbot+1)
- Enable DCM Mode
- Enable DCM Mode
- Css(nF) = 22xTss(mS)
- 1V2 POWER ON LAST
- Css(nF) = 22xTss(mS)
- COPPER ISLAND
- COPPER ISLAND
- Rff(kohm) = Vout/(1Vx20pFxFsw)
- SWITCHABLE
- COPPER PLANE
- Rff(kohm) = Vout/(1Vx20pFxFsw)
- ALWAYS ON
- COPPER PLANE
- Fsw = 400KHz
- Rset = 24(mohm)xIoc/19(uA)
- Fsw = 400KHz
- Rset = 24(mohm)xIoc/19(uA)
- Vout = 0.5x(Rtop/Rbot+1)
- Vout = 0.5x(Rtop/Rbot+1)
- Enable DCM Mode
- Enable DCM Mode
- Css(nF) = 22xTss(mS)
- Css(nF) = 22xTss(mS)
- COPPER ISLAND
- COPPER ISLAND
- MAX 10A
- Rff(kohm) = Vout/(1Vx20pFxFsw)
- SWITCHABLE
- COPPER PLANE
- Rff(kohm) = Vout/(1Vx20pFxFsw)
- ALWAYS ON
- COPPER PLANE
- Fsw = 400KHz
- Rset = 24(mohm)xIoc/19(uA)
- Fsw = 400KHz
- Rset = 13(mohm)xIoc/19(uA)
- Vout = 0.5x(Rtop/Rbot+1)
- Vout = 0.5x(Rtop/Rbot+1)
- Enable DCM Mode
- Enable DCM Mode
- Css(nF) = 22xTss(mS)
- Css(nF) = 22xTss(mS)
- Caution: separate analog and power ground and make connection at GND plane
sheet 34
- SYSTEM POWER CONVERTORs (cont.)
- COPPER ISLAND
- COPPER ISLAND
- Vout = 0.7x(Rtop/Rbot+1)
- SVDD power on with VDD
- Vout = 0.7x(Rtop/Rbot+1)
- XVDD power on with GVDD
